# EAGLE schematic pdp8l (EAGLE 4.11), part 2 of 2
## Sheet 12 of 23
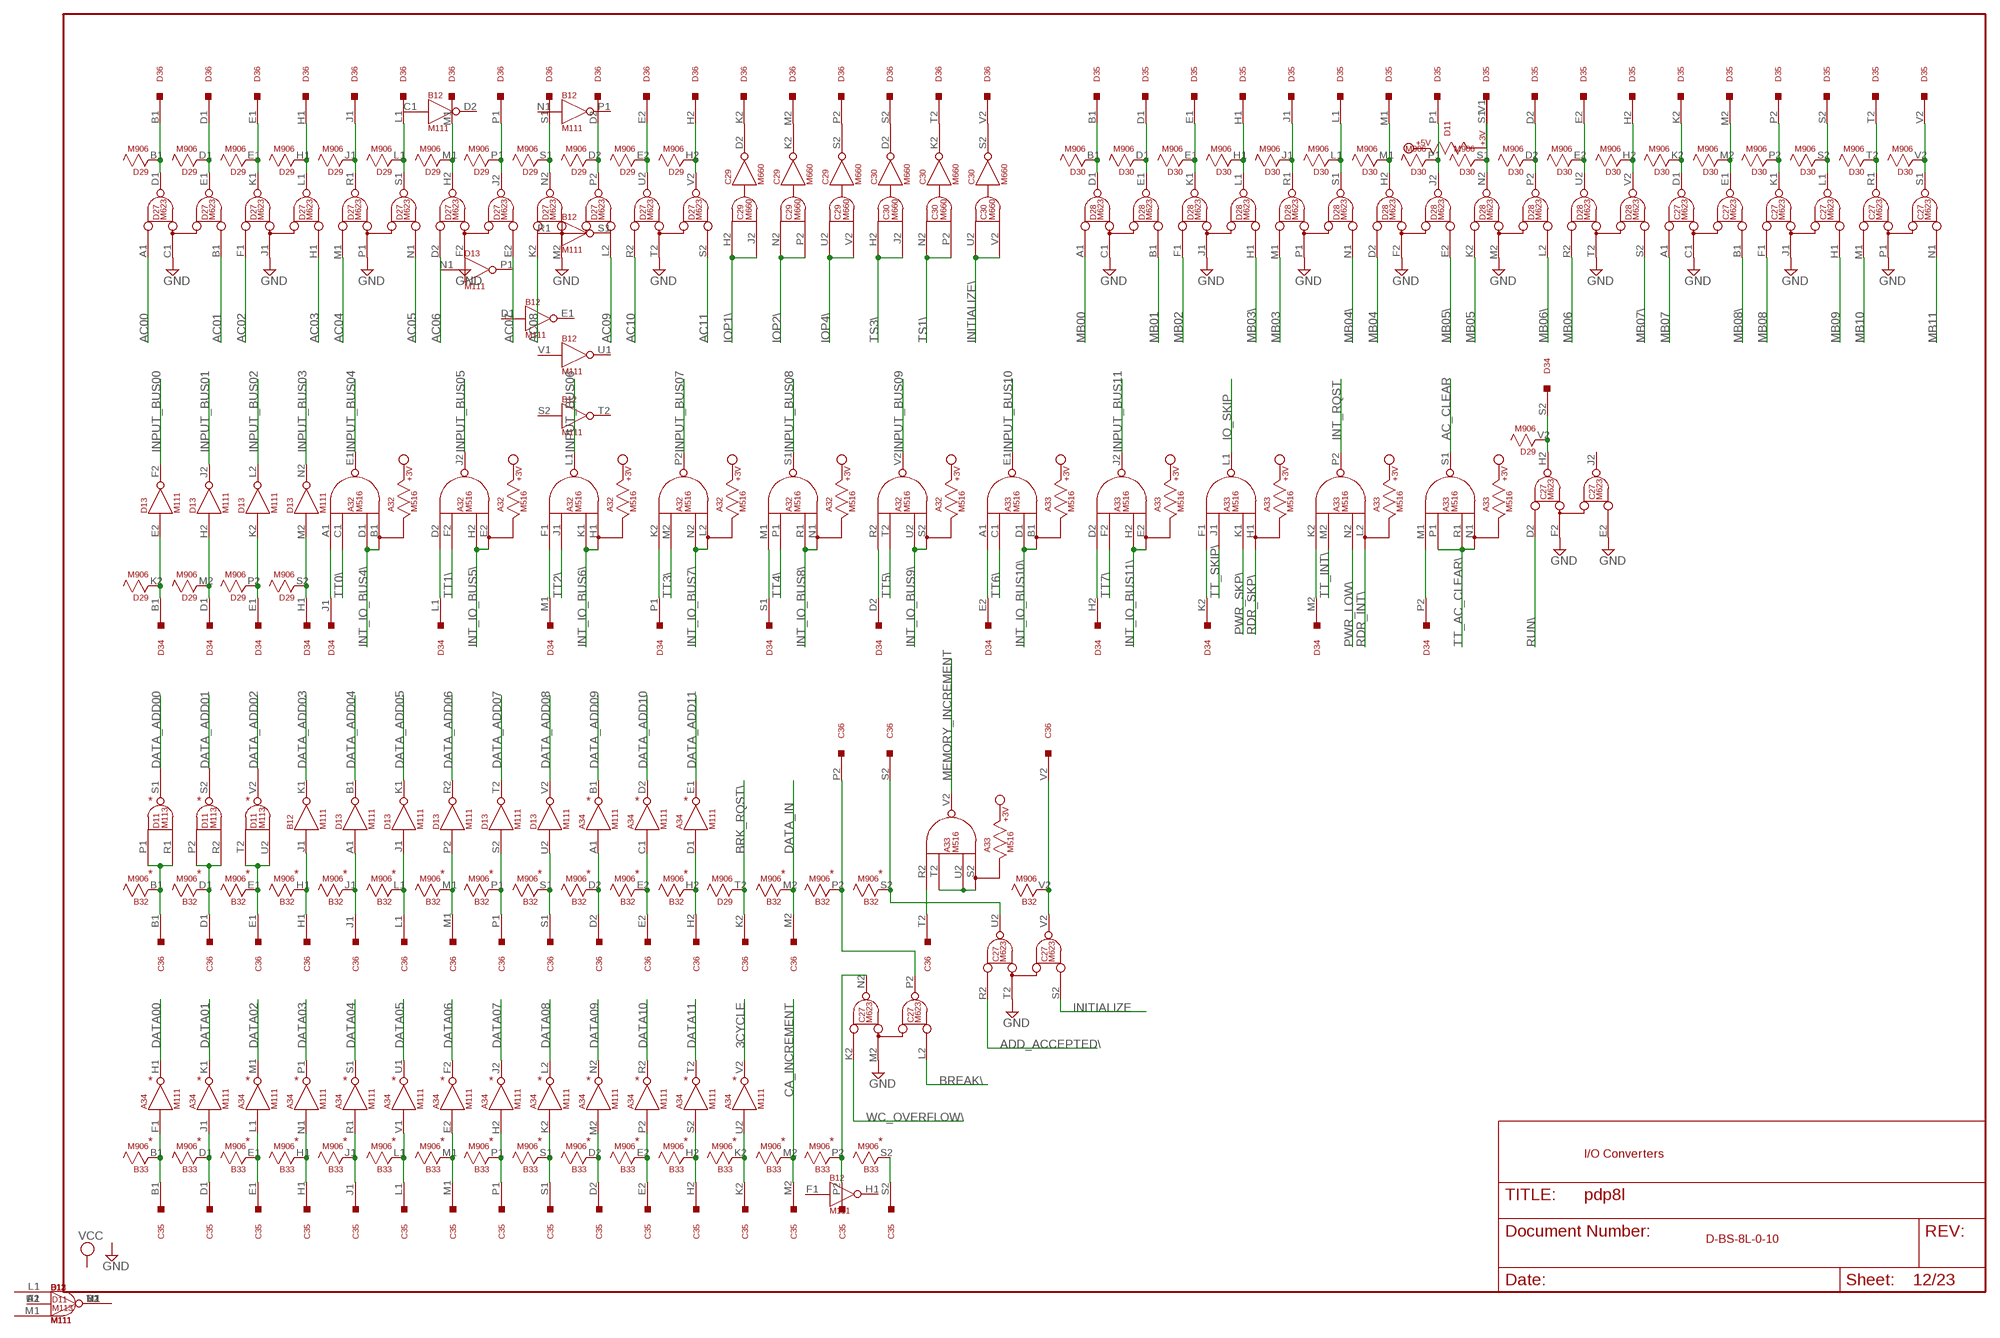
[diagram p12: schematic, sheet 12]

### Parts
A32  M516  [H807]
A33  M516  [H807]
A34  M111  [H807]
B32  M906  [H807]
B33  M906  [H807]
C27  M623  [H807]
C29  M660  [H807]
C30  M660  [H807]
C35  M903  [H807]
C36  M903  [H807]
D27  M623  [H807]
D28  M623  [H807]
D29  M906  [H807]
D30  M906  [H807]
D34  M903  [H807]
D35  M903  [H807]
D36  M903  [H807]

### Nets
3CYCLE: A34.V2(V2:OUT) ; also sheet 2
AC00: D27.A1(D1:A) ; also sheet 5,7
AC01: D27.B1(D1:B) ; also sheet 7
AC02: D27.F1(K1:A) ; also sheet 7
AC03: D27.H1(K1:B) ; also sheet 7
AC04: D27.M1(R1:A) ; also sheet 7,14,21
AC05: D27.N1(R1:B) ; also sheet 7,14,21
AC06: D27.D2(H2:A) ; also sheet 7,14,21
AC07: D27.E2(H2:B) ; also sheet 7,14,21
AC08: D27.K2(N2:A) ; also sheet 7,14,21
AC09: D27.L2(N2:B) ; also sheet 7,14,21
AC10: D27.R2(U2:A) ; also sheet 7,14,21
AC11: D27.S2(U2:B) ; also sheet 7,14,21
AC_CLEAR: A33.S1(S1:OUT) ; also sheet 3
ADD_ACCEPTED\: C27.R2(U2:A) ; also sheet 6
BREAK\: C27.L2(N2:B) ; also sheet 2
BRK_RQST\: C36.K2 D29.T2 ; also sheet 2
CA_INCREMENT: B33.M2 C35.M2 ; also sheet 4
DATA00: A34.H1(H1:OUT) ; also sheet 8
DATA01: A34.K1(K1:OUT) ; also sheet 8
DATA02: A34.M1(M1:OUT) ; also sheet 8
DATA03: A34.P1(P1:OUT) ; also sheet 9
DATA04: A34.S1(S1:OUT) ; also sheet 9
DATA05: A34.U1(U1:OUT) ; also sheet 9
DATA06: A34.F2(F2:OUT) ; also sheet 10
DATA07: A34.J2(J2:OUT) ; also sheet 10
DATA08: A34.L2(L2:OUT) ; also sheet 10
DATA09: A34.N2(N2:OUT) ; also sheet 11
DATA10: A34.R2(R2:OUT) ; also sheet 11
DATA11: A34.T2(T2:OUT) ; also sheet 11
DATA_ADD00: D11.S1(S1:OUT) ; also sheet 8
DATA_ADD01: D11.S2(S2:OUT) ; also sheet 8
DATA_ADD02: D11.V2(V2:OUT) ; also sheet 8
DATA_ADD03: B12.K1(K1:OUT) ; also sheet 9
DATA_ADD04: D13.B1(B1:OUT) ; also sheet 9
DATA_ADD05: D13.K1(K1:OUT) ; also sheet 9
DATA_ADD06: D13.R2(R2:OUT) ; also sheet 10
DATA_ADD07: D13.T2(T2:OUT) ; also sheet 10
DATA_ADD08: D13.V2(V2:OUT) ; also sheet 10
DATA_ADD09: A34.B1(B1:OUT) ; also sheet 11
DATA_ADD10: A34.D2(D2:OUT) ; also sheet 11
DATA_ADD11: A34.E1(E1:OUT) ; also sheet 11
DATA_IN: B32.M2 C36.M2 ; also sheet 3
GND [Supply]: C27.C1(D1:C) C27.E2(H2:B) C27.F2(H2:C) C27.J1(K1:C) C27.M2(N2:C) C27.P1(R1:C) C27.T2(U2:C) D27.C1(D1:C) D27.F2(H2:C) D27.J1(K1:C) D27.M2(N2:C) D27.P1(R1:C) D27.T2(U2:C) D28.C1(D1:C) D28.F2(H2:C) D28.J1(K1:C) D28.M2(N2:C) D28.P1(R1:C) D28.T2(U2:C) ; also sheet 1,3,8,9,10,11,13,14,15,16,19,20,21,23
INITIALIZE: C27.S2(U2:B) ; also sheet 1,13,14
INITIALIZE\: C30.U2(S:IN1) C30.V2(S:IN2) ; also sheet 1,21,22
INPUT_BUS00: D13.F2(F2:OUT) ; also sheet 8
INPUT_BUS01: D13.J2(J2:OUT) ; also sheet 8
INPUT_BUS02: D13.L2(L2:OUT) ; also sheet 8
INPUT_BUS03: D13.N2(N2:OUT) ; also sheet 9
INPUT_BUS04: A32.E1(E1:OUT) ; also sheet 9
INPUT_BUS05: A32.J2(J2:OUT) ; also sheet 9
INPUT_BUS06: A32.L1(L1:OUT) ; also sheet 10
INPUT_BUS07: A32.P2(P2:OUT) ; also sheet 10
INPUT_BUS08: A32.S1(S1:OUT) ; also sheet 10
INPUT_BUS09: A32.V2(V2:OUT) ; also sheet 11
INPUT_BUS10: A33.E1(E1:OUT) ; also sheet 11
INPUT_BUS11: A33.J2(J2:OUT) ; also sheet 11
INT_IO_BUS4\: A32.B1(E1:IN2) A32.D1(E1:IN4) ; also sheet 22
INT_IO_BUS5\: A32.E2(J2:IN2) A32.H2(J2:IN4) ; also sheet 22
INT_IO_BUS6\: A32.H1(L1:IN2) A32.K1(L1:IN4) ; also sheet 22
INT_IO_BUS7\: A32.L2(P2:IN2) A32.N2(P2:IN4) ; also sheet 22
INT_IO_BUS8\: A32.N1(S1:IN2) A32.R1(S1:IN4) ; also sheet 22
INT_IO_BUS9\: A32.S2(V2:IN2) A32.U2(V2:IN4) ; also sheet 22
INT_IO_BUS10\: A33.B1(E1:IN2) A33.D1(E1:IN4) ; also sheet 22
INT_IO_BUS11\: A33.E2(J2:IN2) A33.H2(J2:IN4) ; also sheet 22
INT_RQST: A33.P2(P2:OUT) ; also sheet 6
IO_SKIP: A33.L1(L1:OUT) ; also sheet 5
IOP1\: C29.H2(D:IN1) C29.J2(D:IN2) ; also sheet 1,3
IOP2\: C29.N2(K:IN1) C29.P2(K:IN2) ; also sheet 1,3
IOP4\: C29.U2(S:IN1) C29.V2(S:IN2) ; also sheet 1,3
MB00: D28.A1(D1:A) ; also sheet 7,23
MB01: D28.B1(D1:B) ; also sheet 7,23
MB02: D28.F1(K1:A) ; also sheet 7,23
MB03: D28.M1(R1:A) ; also sheet 2,7,23
MB03\: D28.H1(K1:B) ; also sheet 2,3,6,7,13,14,16,20,21,22,23
MB04: D28.D2(H2:A) ; also sheet 3,7,23
MB04\: D28.N1(R1:B) ; also sheet 3,6,7,13,14,20,21,22,23
MB05: D28.K2(N2:A) ; also sheet 3,5,7,20,23
MB05\: D28.E2(H2:B) ; also sheet 3,6,7,13,14,21,22,23
MB06: D28.R2(U2:A) ; also sheet 3,5,7,14,23
MB06\: D28.L2(N2:B) ; also sheet 3,6,7,13,20,21,22,23
MB07: C27.A1(D1:A) ; also sheet 3,5,7,13,21,23
MB07\: D28.S2(U2:B) ; also sheet 3,6,7,14,20,22,23
MB08: C27.F1(K1:A) ; also sheet 4,5,7,13,22,23
MB08\: C27.B1(D1:B) ; also sheet 4,5,6,7,14,16,20,21,23
MB09: C27.H1(K1:B) ; also sheet 1,3,4,7,23
MB10: C27.M1(R1:A) ; also sheet 1,4,7,23
MB11: C27.N1(R1:B) ; also sheet 1,4,7,23
MEMORY_INCREMENT: A33.V2(V2:OUT) ; also sheet 4,6
N$113: C30.S2(S:OUT) D36.V2
N$114: C30.K2(K:OUT) D36.T2
N$115: C30.D2(D:OUT) D36.S2
N$117: C29.S2(S:OUT) D36.P2
N$118: C29.K2(K:OUT) D36.M2
N$119: C29.D2(D:OUT) D36.K2
N$120: D27.D1(D1:D) D29.B1 D36.B1
N$121: D27.E1(D1:E) D29.D1 D36.D1
N$122: D27.K1(K1:D) D29.E1 D36.E1
N$124: D27.L1(K1:E) D29.H1 D36.H1
N$125: D27.R1(R1:D) D29.J1 D36.J1
N$126: D27.S1(R1:E) D29.L1 D36.L1
N$127: D27.H2(H2:D) D29.M1 D36.M1
N$128: D27.J2(H2:E) D29.P1 D36.P1
N$129: D27.N2(N2:D) D29.S1 D36.S1
N$130: D27.P2(N2:E) D29.D2 D36.D2
N$131: D27.U2(U2:D) D29.E2 D36.E2
N$132: D27.V2(U2:E) D29.H2 D36.H2
N$133: D28.D1(D1:D) D30.B1 D35.B1
N$134: D28.E1(D1:E) D30.D1 D35.D1
N$135: D28.K1(K1:D) D30.E1 D35.E1
N$136: D28.L1(K1:E) D30.H1 D35.H1
N$137: D28.R1(R1:D) D30.J1 D35.J1
N$138: D28.S1(R1:E) D30.L1 D35.L1
N$139: D28.H2(H2:D) D30.M1 D35.M1
N$140: D28.J2(H2:E) D30.P1 D35.P1
N$141: D28.N2(N2:D) D30.S1 D35.S1
N$142: D28.P2(N2:E) D30.D2 D35.D2
N$143: D28.U2(U2:D) D30.E2 D35.E2
N$144: D28.V2(U2:E) D30.H2 D35.H2
N$145: C27.D1(D1:D) D30.K2 D35.K2
N$146: C27.E1(D1:E) D30.M2 D35.M2
N$147: C27.K1(K1:D) D30.P2 D35.P2
N$148: C27.L1(K1:E) D30.S2 D35.S2
N$149: C27.R1(R1:D) D30.T2 D35.T2
N$150: C27.S1(R1:E) D30.V2 D35.V2
N$151: D13.E2(F2:IN) D29.K2 D34.B1
N$152: D13.H2(J2:IN) D29.M2 D34.D1
N$153: D13.K2(L2:IN) D29.P2 D34.E1
N$154: D13.M2(N2:IN) D29.S2 D34.H1
N$155: A32.A1(E1:IN) D34.J1
N$156: A32.D2(J2:IN) D34.L1
N$157: B32.B1 C36.B1 D11.P1(S1:IN1) D11.R1(S1:IN2)
N$158: B32.D1 C36.D1 D11.P2(S2:IN1) D11.R2(S2:IN2)
N$159: A32.F1(L1:IN) D34.M1
N$160: B32.E1 C36.E1 D11.T2(V2:IN1) D11.U2(V2:IN2)
N$161: A33.R2(V2:IN) C36.T2
N$162: A32.K2(P2:IN) D34.P1
N$163: A33.S2(V2:IN2) A33.T2(V2:IN3) A33.U2(V2:IN4)
N$164: B32.J1 C36.J1 D13.A1(B1:IN)
N$165: A32.M1(S1:IN) D34.S1
N$166: C27.H2(H2:D) D29.V2 D34.S2
N$167: B12.J1(K1:IN) B32.H1 C36.H1
N$168: B32.L1 C36.L1 D13.J1(K1:IN)
N$169: B32.M1 C36.M1 D13.P2(R2:IN)
N$170: A32.R2(V2:IN) D34.D2
N$171: B32.P1 C36.P1 D13.S2(T2:IN)
N$172: A33.A1(E1:IN) D34.E2
N$173: B32.S1 C36.S1 D13.U2(V2:IN)
N$174: A34.A1(B1:IN) B32.D2 C36.D2
N$175: A33.D2(J2:IN) D34.H2
N$176: A34.C1(D2:IN) B32.E2 C36.E2
N$177: A34.D1(E1:IN) B32.H2 C36.H2
N$178: B32.P2 C27.P2(N2:E) C36.P2
N$179: B32.S2 C27.U2(U2:D) C36.S2
N$180: A33.F1(L1:IN) D34.K2
N$181: B32.V2 C27.V2(U2:E) C36.V2
N$182: A34.F1(H1:IN) B33.B1 C35.B1
N$183: A34.J1(K1:IN) B33.D1 C35.D1
N$184: A33.M1(S1:IN) D34.P2
N$185: A34.L1(M1:IN) B33.E1 C35.E1
N$186: A33.K2(P2:IN) D34.M2
N$187: A34.N1(P1:IN) B33.H1 C35.H1
N$188: A34.R1(S1:IN) B33.J1 C35.J1
N$189: A34.V1(U1:IN) B33.L1 C35.L1
N$190: A34.E2(F2:IN) B33.M1 C35.M1
N$191: A34.H2(J2:IN) B33.P1 C35.P1
N$192: A34.K2(L2:IN) B33.S1 C35.S1
N$193: A34.M2(N2:IN) B33.D2 C35.D2
N$194: A34.P2(R2:IN) B33.E2 C35.E2
N$195: A34.S2(T2:IN) B33.H2 C35.H2
N$196: A34.U2(V2:IN) B33.K2 C35.K2
N$198: B33.P2 C27.N2(N2:D) C35.P2
N$199: B33.S2 C35.S2
PWR_LOW\: A33.N2(P2:IN4) ; also sheet 20
PWR_SKP\: A33.K1(L1:IN4) ; also sheet 20
RDR_INT\: A33.L2(P2:IN2) ; also sheet 21,22
RDR_SKP\: A33.H1(L1:IN2) ; also sheet 21,22
RUN\: C27.D2(H2:A) ; also sheet 1
TS1\: C30.N2(K:IN1) C30.P2(K:IN2) ; also sheet 1
TS3\: C30.H2(D:IN1) C30.J2(D:IN2) ; also sheet 1
TT0\: A32.C1(E1:IN3) ; also sheet 13
TT1\: A32.F2(J2:IN3) ; also sheet 13
TT2\: A32.J1(L1:IN3) ; also sheet 13
TT3\: A32.M2(P2:IN3) ; also sheet 13
TT4\: A32.P1(S1:IN3) ; also sheet 13
TT5\: A32.T2(V2:IN3) ; also sheet 13
TT6\: A33.C1(E1:IN3) ; also sheet 13
TT7\: A33.F2(J2:IN3) ; also sheet 13
TT_AC_CLEAR\: A33.N1(S1:IN2) A33.P1(S1:IN3) A33.R1(S1:IN4) ; also sheet 13
TT_INT\: A33.M2(P2:IN3) ; also sheet 14
TT_SKIP\: A33.J1(L1:IN3) ; also sheet 14
WC_OVERFLOW\: C27.K2(N2:A) ; also sheet 6
Unconnected: B32.K2 B32.T2 B33.T2 B33.V2 C27.J2(H2:E) C35.T2 C35.V2 D34.T2 D34.V2

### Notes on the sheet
- * | * | * | * | * | *
- * | * | * | * | * | * | * | * | * | * | * | * | * | * | *
- * | * | * | * | * | * | * | * | * | * | * | * | *
- * | * | * | * | * | * | * | * | * | * | * | * | * | * | * | *
- I/O Converters
- D-BS-8L-0-10

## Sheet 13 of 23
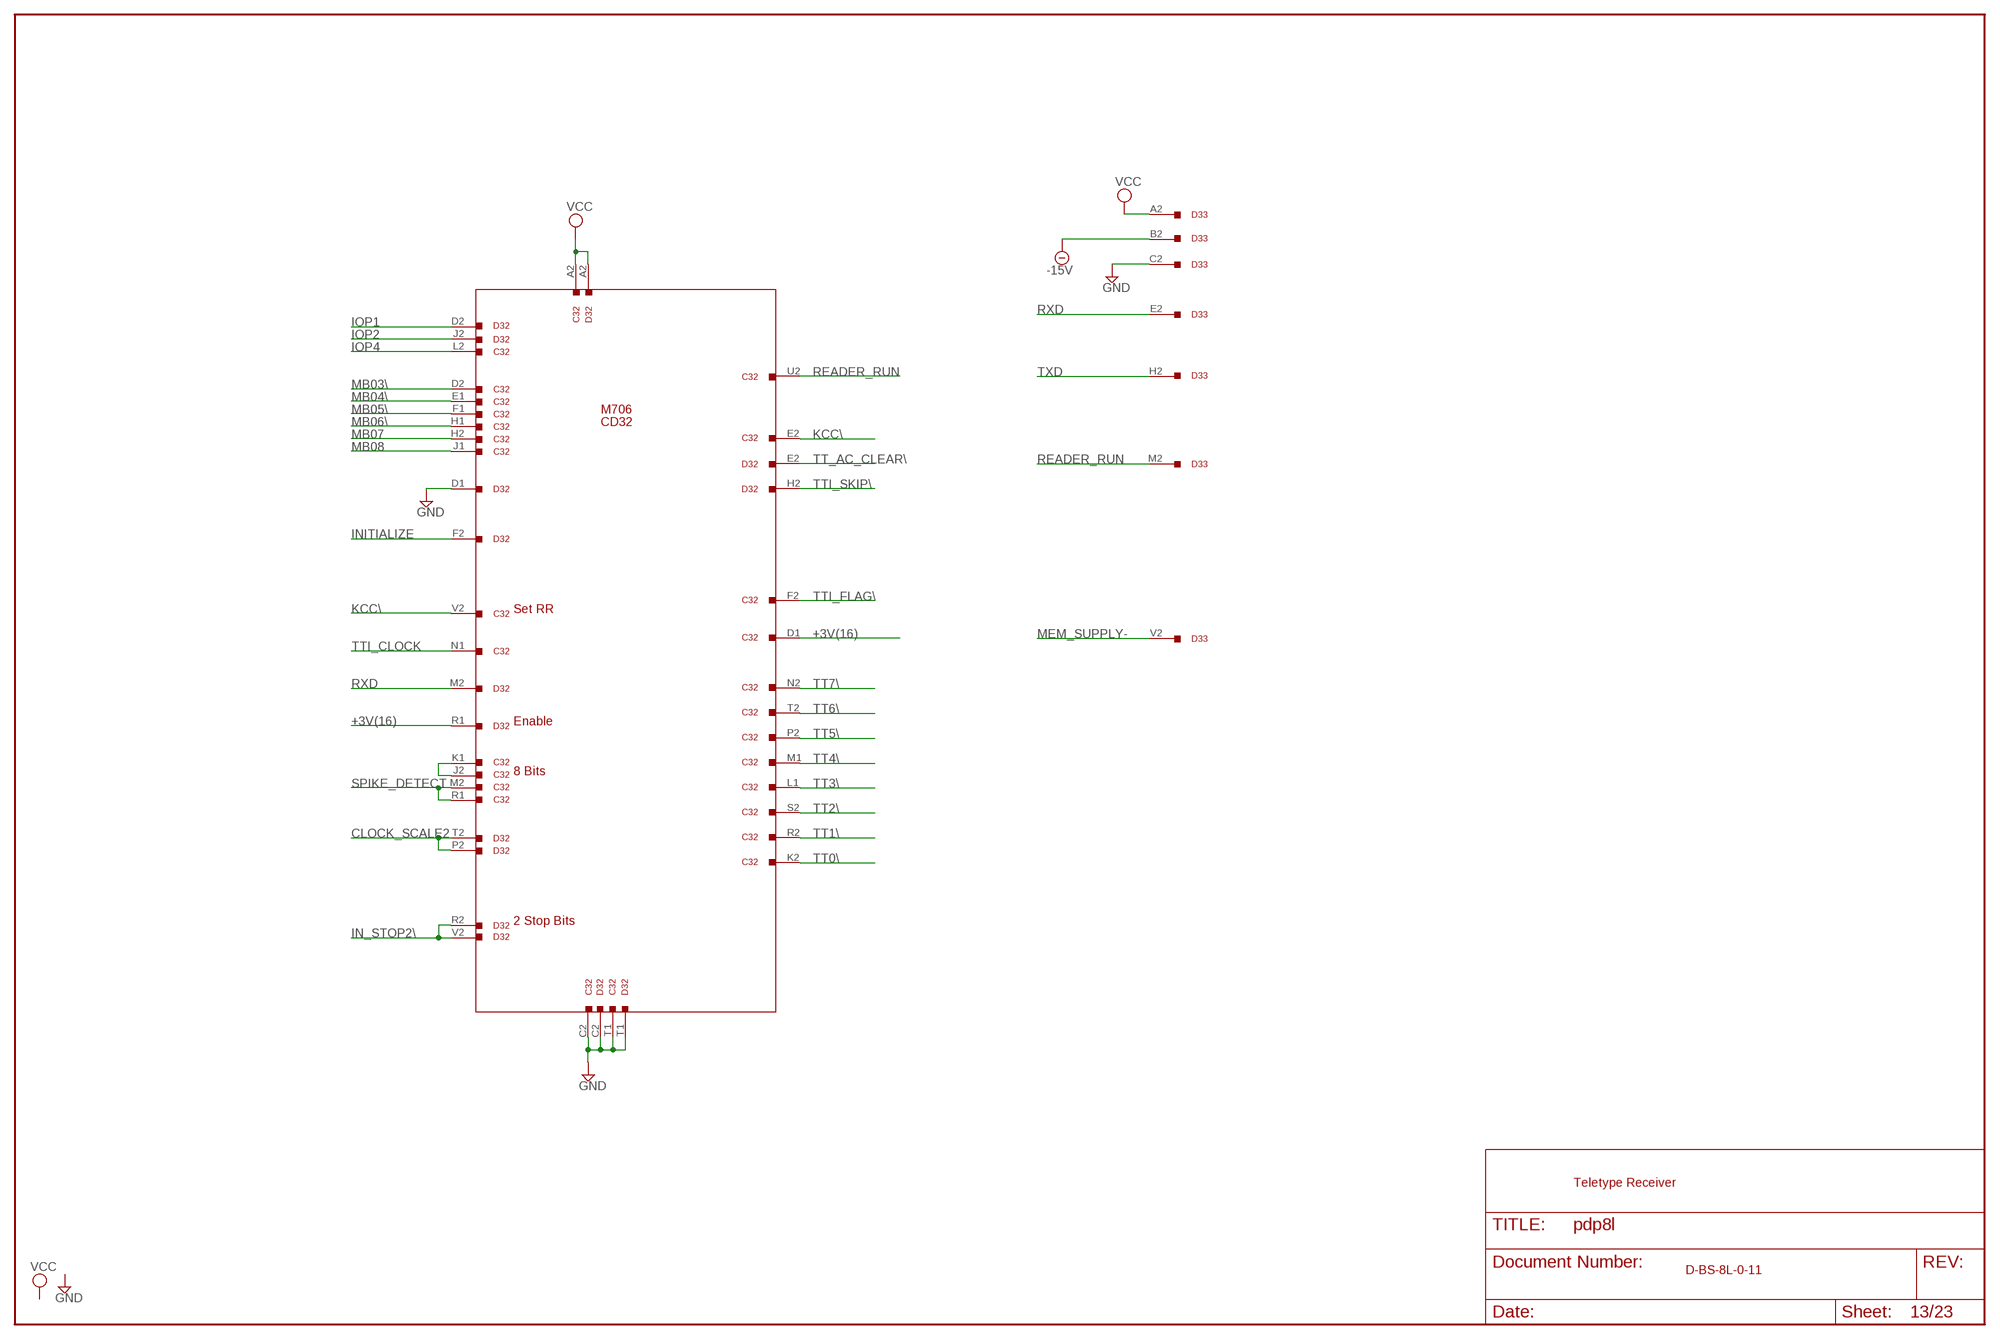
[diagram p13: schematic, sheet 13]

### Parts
C32  M916  [H807]
D32  M916  [H807]
D33  W076  W023  [H807]

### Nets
+3V(16): C32.D1 D32.R1
-15V [Supply]: D33.B2 ; also sheet 22
CLOCK_SCALE2: D32.P2 D32.T2
GND [Supply]: C32.C2 C32.T1 D32.C2 D32.D1 D32.T1 D33.C2 ; also sheet 1,3,8,9,10,11,12,14,15,16,19,20,21,23
IN_STOP2\: D32.R2 D32.V2
INITIALIZE: D32.F2 ; also sheet 1,12,14
IOP1: D32.D2 ; also sheet 1,14,21,22,23
IOP2: D32.J2 ; also sheet 1,14,20,21,22
IOP4: C32.L2 ; also sheet 1,14,21,22,23
KCC\: C32.E2 C32.V2
MB03\: C32.D2 ; also sheet 2,3,6,7,12,14,16,20,21,22,23
MB04\: C32.E1 ; also sheet 3,6,7,12,14,20,21,22,23
MB05\: C32.F1 ; also sheet 3,6,7,12,14,21,22,23
MB06\: C32.H1 ; also sheet 3,6,7,12,20,21,22,23
MB07: C32.H2 ; also sheet 3,5,7,12,21,23
MB08: C32.J1 ; also sheet 4,5,7,12,22,23
MEM_SUPPLY- [Supply]: D33.V2 ; also sheet 15,16
N$200: C32.J2 C32.K1
READER_RUN: C32.U2 D33.M2
RXD: D32.M2 D33.E2
SPIKE_DETECT: C32.M2 C32.R1
TT0\: C32.K2 ; also sheet 12
TT1\: C32.R2 ; also sheet 12
TT2\: C32.S2 ; also sheet 12
TT3\: C32.L1 ; also sheet 12
TT4\: C32.M1 ; also sheet 12
TT5\: C32.P2 ; also sheet 12
TT6\: C32.T2 ; also sheet 12
TT7\: C32.N2 ; also sheet 12
TT_AC_CLEAR\: D32.E2 ; also sheet 12
TTI_CLOCK: C32.N1 ; also sheet 14
TTI_FLAG\: C32.F2 ; also sheet 14
TTI_SKIP\: D32.H2 ; also sheet 14
TXD: D33.H2 ; also sheet 14
VCC [Supply]: C32.A2 D32.A2 D33.A2 ; also sheet 14,15,19,20
Unconnected: C32.A1 C32.B1 C32.B2 C32.C1 C32.P1 C32.S1 C32.U1 C32.V1 D32.A1 D32.B1 D32.B2 D32.C1 D32.E1 D32.F1 D32.H1 D32.J1 D32.K1 D32.K2 D32.L1 D32.L2 D32.M1 D32.N1 D32.N2 D32.P1 D32.S1 D32.S2 D32.U1 D32.U2 D32.V1 D33.D2 D33.F2 D33.J2 D33.K2 D33.L2 D33.N2 D33.P2 D33.R2 D33.S2 D33.T2 D33.U2

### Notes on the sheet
- M706
- CD32
- Set RR
- Enable
- 8 Bits
- 2 Stop Bits
- Teletype Receiver
- D-BS-8L-0-11

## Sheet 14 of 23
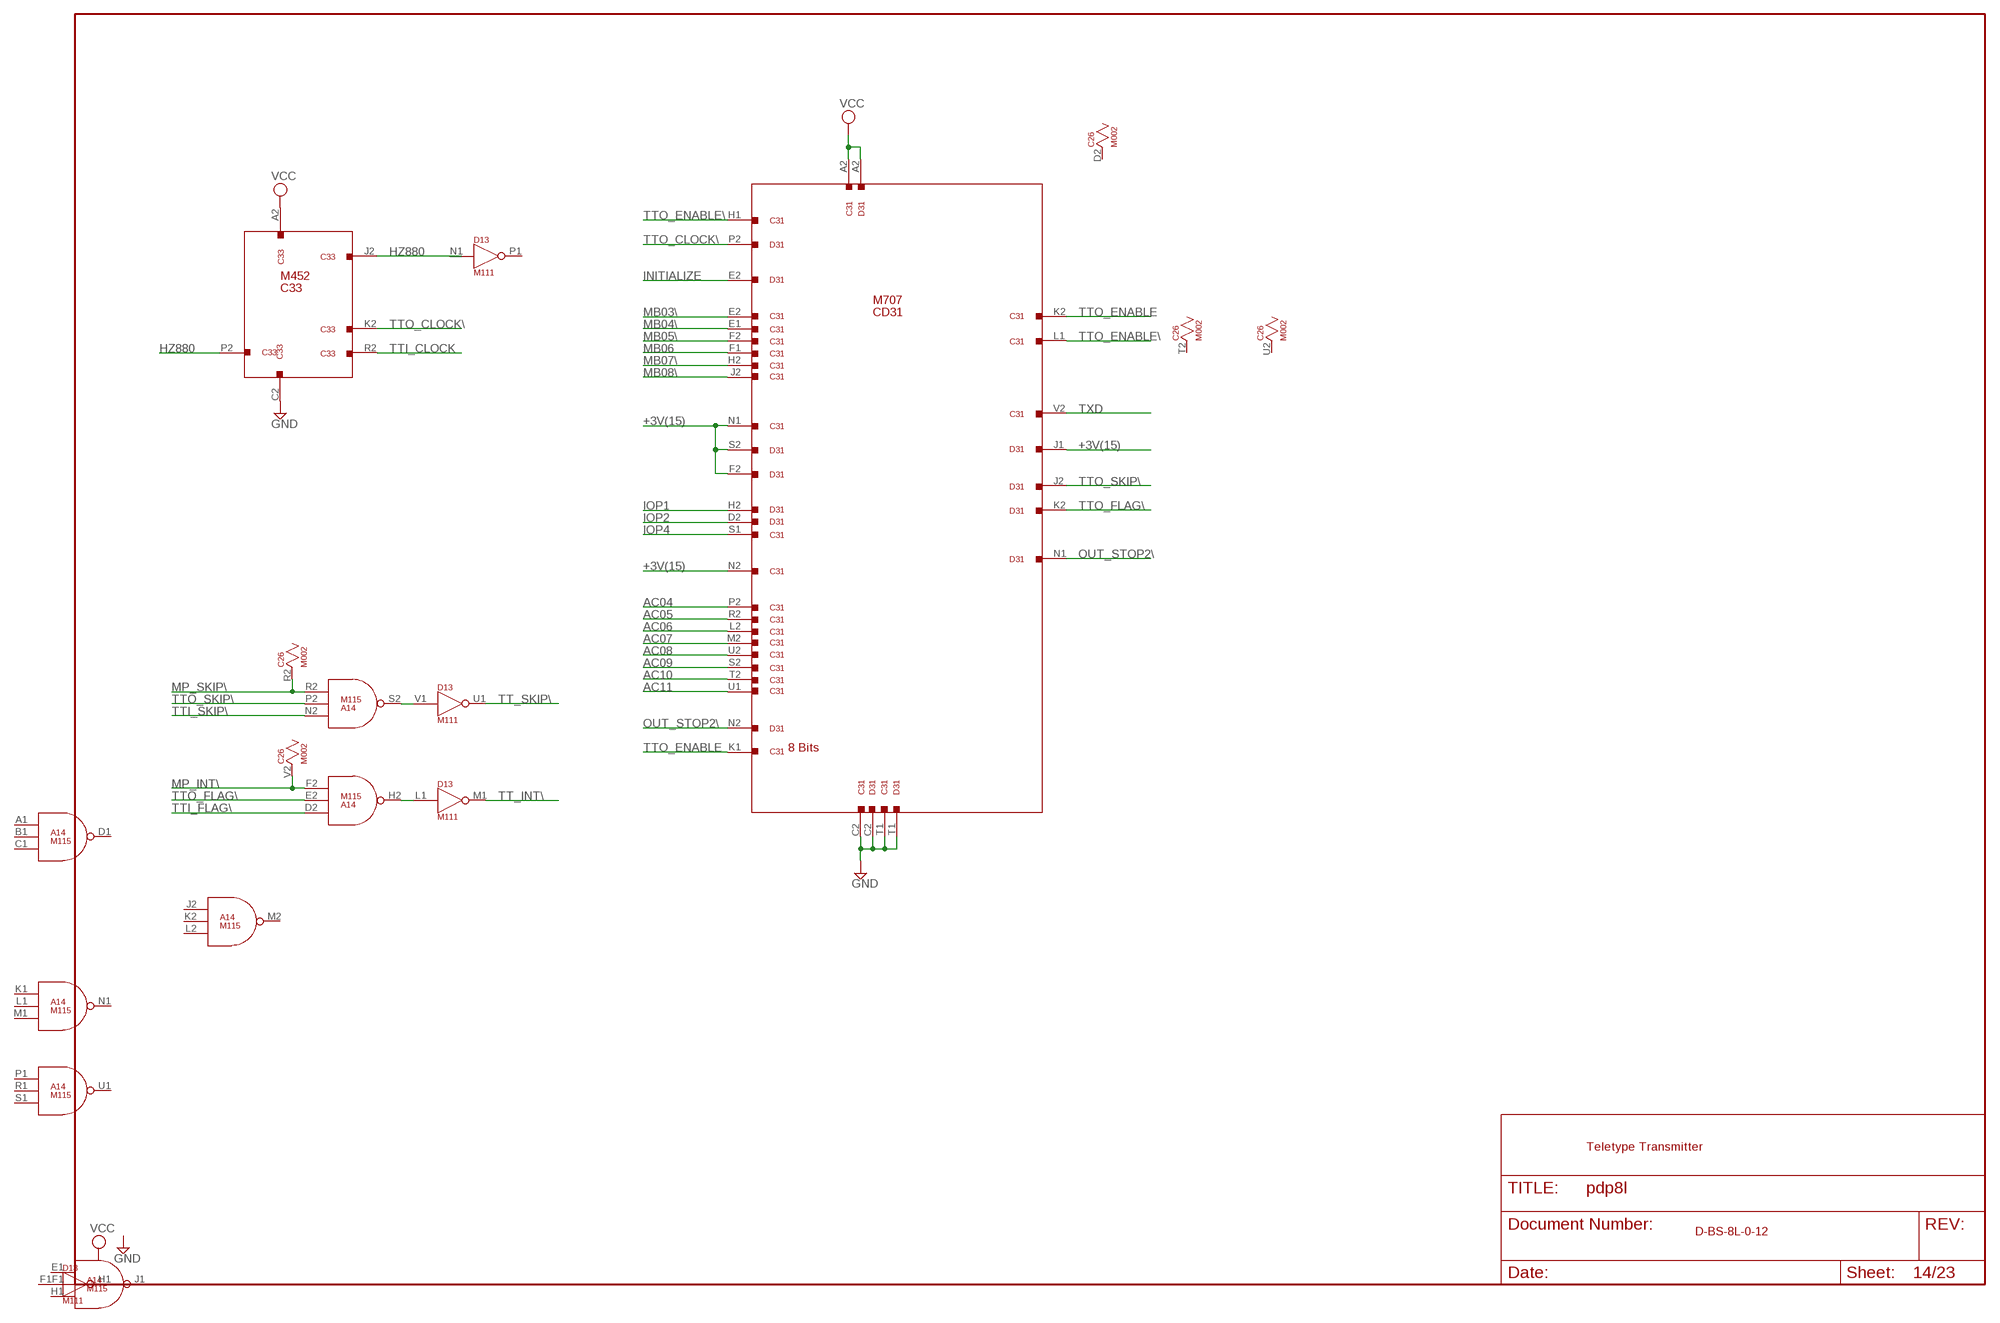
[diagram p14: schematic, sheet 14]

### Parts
C31  M916  [H807]
C33  W023  [H807]
D31  M916  [H807]

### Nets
+3V(15): C31.N1 C31.N2 D31.F2 D31.J1 D31.S2
AC04: C31.P2 ; also sheet 7,12,21
AC05: C31.R2 ; also sheet 7,12,21
AC06: C31.L2 ; also sheet 7,12,21
AC07: C31.M2 ; also sheet 7,12,21
AC08: C31.U2 ; also sheet 7,12,21
AC09: C31.S2 ; also sheet 7,12,21
AC10: C31.T2 ; also sheet 7,12,21
AC11: C31.U1 ; also sheet 7,12,21
GND [Supply]: C31.C2 C31.T1 C33.C2 D31.C2 D31.T1 ; also sheet 1,3,8,9,10,11,12,13,15,16,19,20,21,23
HZ880: C33.J2 C33.P2
INITIALIZE: D31.E2 ; also sheet 1,12,13
IOP1: D31.H2 ; also sheet 1,13,21,22,23
IOP2: D31.D2 ; also sheet 1,13,20,21,22
IOP4: C31.S1 ; also sheet 1,13,21,22,23
MB03\: C31.E2 ; also sheet 2,3,6,7,12,13,16,20,21,22,23
MB04\: C31.E1 ; also sheet 3,6,7,12,13,20,21,22,23
MB05\: C31.F2 ; also sheet 3,6,7,12,13,21,22,23
MB06: C31.F1 ; also sheet 3,5,7,12,23
MB07\: C31.H2 ; also sheet 3,6,7,12,20,22,23
MB08\: C31.J2 ; also sheet 4,5,6,7,12,16,20,21,23
MP_INT\: A14.F2(H2:IN3) C26.V2 ; also sheet 23
MP_SKIP\: A14.R2(S2:IN3) C26.R2 ; also sheet 23
N$108: A14.S2(S2:OUT) D13.V1(U1:IN)
N$197: A14.H2(H2:OUT) D13.L1(M1:IN)
OUT_STOP2\: D31.N1 D31.N2
TT_INT\: D13.M1(M1:OUT) ; also sheet 12
TT_SKIP\: D13.U1(U1:OUT) ; also sheet 12
TTI_CLOCK: C33.R2 ; also sheet 13
TTI_FLAG\: A14.D2(H2:IN1) ; also sheet 13
TTI_SKIP\: A14.N2(S2:IN1) ; also sheet 13
TTO_CLOCK\: C33.K2 D31.P2
TTO_ENABLE: C31.K1 C31.K2
TTO_ENABLE\: C31.H1 C31.L1
TTO_FLAG\: A14.E2(H2:IN2) D31.K2
TTO_SKIP\: A14.P2(S2:IN2) D31.J2
TXD: C31.V2 ; also sheet 13
VCC [Supply]: C31.A2 C33.A2 D31.A2 ; also sheet 13,15,19,20
Unconnected: C31.A1 C31.B1 C31.B2 C31.C1 C31.D1 C31.D2 C31.J1 C31.M1 C31.P1 C31.R1 C31.V1 C33.B2 C33.D2 C33.E2 C33.F2 C33.H2 C33.L2 C33.M2 C33.N2 C33.S2 C33.T2 C33.U2 C33.V2 D31.A1 D31.B1 D31.B2 D31.C1 D31.D1 D31.E1 D31.F1 D31.H1 D31.K1 D31.L1 D31.L2 D31.M1 D31.M2 D31.P1 D31.R1 D31.R2 D31.S1 D31.T2 D31.U1 D31.U2 D31.V1 D31.V2

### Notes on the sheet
- M452
- C33
- M707
- CD31
- 8 Bits
- Teletype Transmitter
- D-BS-8L-0-12

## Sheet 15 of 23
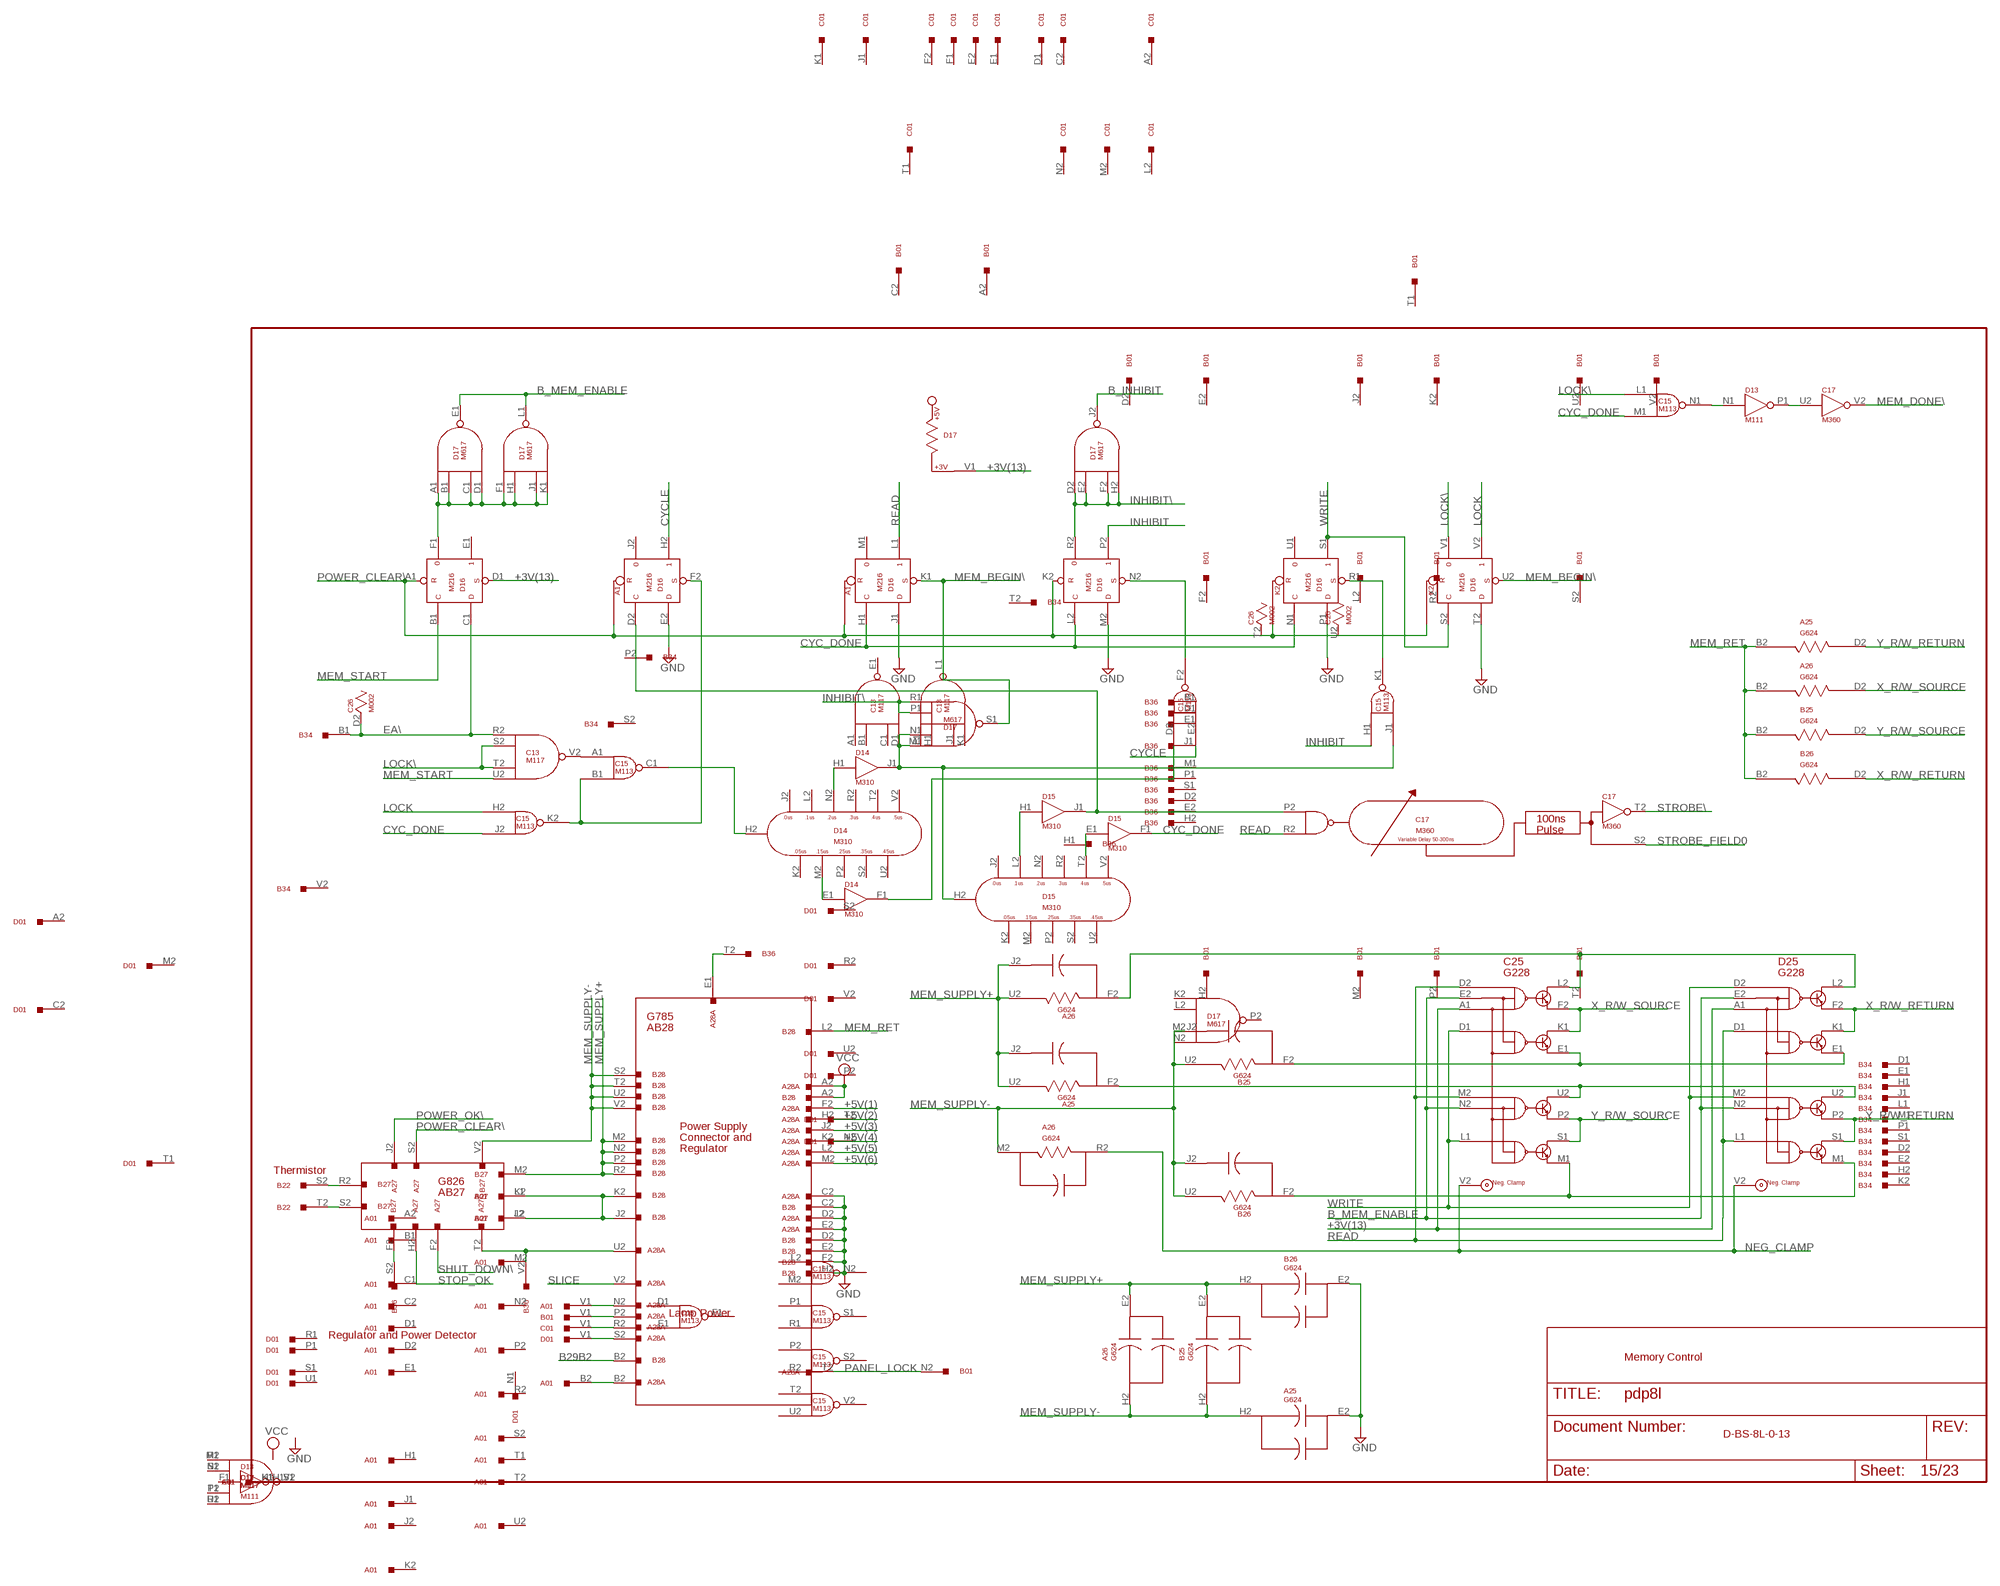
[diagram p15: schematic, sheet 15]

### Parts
A25  G624  [H807]
A26  G624  [H807]
A27  G826A  W023  [H807]
A28A  M916  [H807]
B22  W025B  W023  [H807]
B25  G624  [H807]
B26  G624  [H807]
B27  G826B  W023  [H807]
B28  G785B  W023  [H807]
C17  M360  [H807]
C25  G228  [H807]
D14  M310  [H807]
D15  M310  [H807]
D16  M216  M206X  [H807]
D17  M617  [H807]
D25  G228  [H807]

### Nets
+3V(13): C25.A1 D16.D1(E1:S) D17.V1 D25.A1 ; also sheet 5
+5V(1) [Supply]: A28A.F2
+5V(2) [Supply]: A28A.H2
+5V(3) [Supply]: A28A.J2
+5V(4) [Supply]: A28A.K2
+5V(5) [Supply]: A28A.L2
+5V(6) [Supply]: A28A.M2
A01B2 [Supply]: A01.B2 A28A.B2
A01V1 [Supply]: A01.V1 A28A.N2
B01V1 [Supply]: A28A.P2 B01.V1
B29B2 [Supply]: B28.B2 ; also sheet 22
B_INHIBIT: D17.J2(J2:OUT) ; also sheet 16
B_MEM_ENABLE: C25.E2 C25.N2 D17.E1(E1:OUT) D17.L1(L1:OUT) D25.E2 D25.N2 ; also sheet 16,17,18
C01V1 [Supply]: A28A.R2 C01.V1
CYC_DONE: C15.J2(K2:IN2) C15.M1(N1:IN2) D15.F1(F1:OUT) D16.H1(L1:C) D16.L2(P2:C) D16.N1(S1:C)
CYCLE: C15.E2(F2:IN2) D16.H2
D01V1 [Supply]: A28A.S2 D01.V1
EA\: B34.B1 C13.R2(V2:IN1) C26.D2 D16.C1(E1:D)
GND [Supply]: A25.E2 A28A.C2 A28A.D2 A28A.E2 B26.E2 B28.C2 B28.D2 B28.E2 B28.F2 B28.H2 D16.E2(H2:D) D16.J1(L1:D) D16.M2(P2:D) D16.P1(S1:D) D16.T2(V2:D) ; also sheet 1,3,8,9,10,11,12,13,14,16,19,20,21,23
INHIBIT: C15.H1(K1:IN1) D16.P2
INHIBIT\: D16.R2 D17.D2(J2:IN1) D17.E2(J2:IN2) D17.F2(J2:IN3) D17.H2(J2:IN4) D17.P1(S1:IN3) D17.R1(S1:IN4)
LOCK: C15.H2(K2:IN1) D16.V2
LOCK\: C13.S2(V2:IN2) C13.T2(V2:IN3) C15.L1(N1:IN1) D16.V1
MEM_BEGIN\: D16.K1(L1:S) D16.U2(V2:S) D17.S1(S1:OUT) ; also sheet 16
MEM_DONE\: C17.V2(V:OUT) ; also sheet 1,6
MEM_RET [Supply]: A25.B2 A26.B2 B25.B2 B26.B2 B28.L2
MEM_START: C13.U2(V2:IN4) D16.B1(E1:C) ; also sheet 1
MEM_SUPPLY+ [Supply]: A25.J2 A25.U2 A26.E2 A26.J2 A26.U2 B25.E2 B26.H2 B27.M2 B28.M2 B28.N2 B28.P2 B28.R2 ; also sheet 16
MEM_SUPPLY- [Supply]: A25.H2 A26.H2 A26.M2 B25.H2 B25.J2 B25.U2 B26.J2 B26.U2 B27.V2 B28.S2 B28.T2 B28.U2 B28.V2 ; also sheet 13,16
N$201: D16.F1 D17.A1(E1:IN1) D17.B1(E1:IN2) D17.C1(E1:IN3) D17.D1(E1:IN4) D17.F1(L1:IN1) D17.H1(L1:IN2) D17.J1(L1:IN3) D17.K1(L1:IN4)
N$203: C13.V2(V2:OUT) C15.A1(C1:IN1)
N$204: C15.B1(C1:IN2) C15.K2(K2:OUT) D16.F2(H2:S)
N$205: C15.C1(C1:OUT) D14.H2(H2:H2)
N$206: C17.P2(T:P) D15.J1(J1:OUT) D16.D2(H2:C)
N$207: C15.F2(F2:OUT) D16.N2(P2:S)
N$208: D14.H1(J1:IN) D14.N2(H2:N2)
N$209: D14.E1(F1:IN) D14.M2(H2:M2)
N$210: C15.J1(K1:IN2) D14.J1(J1:OUT) D15.H2(H2:H2) D17.M1(S1:IN1) D17.N1(S1:IN2)
N$211: D15.H1(J1:IN) D15.L2(H2:L2)
N$212: D15.E1(F1:IN) D15.T2(H2:T2)
N$213: C15.K1(K1:OUT) D16.R1(S1:S)
N$214: B22.T2 B27.S2
N$215: C15.D2(F2:IN1) D14.F1(F1:OUT)
N$216: B22.S2 B27.R2
N$217: B27.F2 B36.S2
N$218: A27.T2 A28A.U2 B36.V2
N$219: B27.J2 B27.K2 B28.J2 B28.K2
N$221: A26.F2 C25.L2 D25.L2
N$222: C17.U2(V:IN) D13.P1(P1:OUT)
N$223: C15.N1(N1:OUT) D13.N1(P1:IN)
N$224: B26.F2 C25.M1 D25.M1
N$225: B25.F2 C25.E1 D25.E1
N$226: A25.F2 C25.U2 D25.U2
N$414: A28A.E1 B36.T2
NEG_CLAMP: A26.R2 C25.V2 D25.V2 ; also sheet 17,18
PANEL_LOCK: A28A.T2 B01.N2
POWER_CLEAR\: A27.S2 D16.A1(E1:R) D16.K2(P2:R) ; also sheet 1
POWER_OK\: A27.J2 ; also sheet 1
READ: C17.R2(T:R) C25.D2 C25.M2 D16.L1 D25.D1 D25.L1
SHUT_DOWN\: A27.F2 ; also sheet 20
SLICE: A28A.V2 ; also sheet 16
STOP_OK: A27.H2 ; also sheet 1,20
STROBE\: C17.T2(T:T) ; also sheet 1,6
STROBE_FIELD0: C17.S2(T:S) ; also sheet 16
VCC [Supply]: A28A.A2 B28.A2 ; also sheet 13,14,19,20
WRITE: C25.D1 C25.L1 D16.S1 D16.S2(V2:C) D25.D2 D25.M2
X_R/W_RETURN: B26.D2 D25.F2 D25.K1 ; also sheet 17
X_R/W_SOURCE: A26.D2 C25.F2 C25.K1 ; also sheet 17
Y_R/W_RETURN: A25.D2 D25.P2 D25.S1 ; also sheet 18
Y_R/W_SOURCE: B25.D2 C25.P2 C25.S1 ; also sheet 18
Unconnected: A25.C2 A25.V2 A26.C2 A26.K2 A26.L2 A26.S2 A26.T2 A26.V2 A27.A2 A27.B2 A27.C2 A27.D2 A27.E2 A27.K2 A27.L2 A27.M2 A27.N2 A27.P2 A27.R2 A27.U2 A27.V2 A28A.A1 A28A.B1 A28A.C1 A28A.D1 A28A.F1 A28A.H1 A28A.J1 A28A.K1 A28A.L1 A28A.M1 A28A.N1 A28A.P1 A28A.R1 A28A.S1 A28A.T1 A28A.U1 A28A.V1 B22.A2 B22.B2 B22.U2 B22.V2 B25.C2 B25.V2 B26.C2 B26.V2 B27.A2 B27.B2 B27.C2 B27.D2 B27.E2 B27.H2 B27.L2 B27.N2 B27.P2 B27.T2 B27.U2 C25.F1(F1:H) C25.H1(F1:J) C25.H2(H2:H) C25.J1(F1:K) C25.J2(H2:J) C25.K2(H2:K) C25.N1(N1:H) C25.P1(N1:J) C25.R1(N1:K) C25.R2(R2:H) C25.S2(R2:J) C25.T2(R2:K) D14.J2(H2:J2) D14.K2(H2:K2) D14.L2(H2:L2) D14.P2(H2:P2) D14.R2(H2:R2) D14.S2(H2:S2) D14.T2(H2:T2) D14.U2(H2:U2) D14.V2(H2:V2) D15.J2(H2:J2) D15.K2(H2:K2) D15.M2(H2:M2) D15.N2(H2:N2) D15.P2(H2:P2) D15.R2(H2:R2) D15.S2(H2:S2) D15.U2(H2:U2) D15.V2(H2:V2) D16.E1 D16.J2 D16.M1 D16.U1 D17.U1 D25.F1(F1:H) D25.H1(F1:J) D25.H2(H2:H) D25.J1(F1:K) D25.J2(H2:J) D25.K2(H2:K) D25.N1(N1:H) D25.P1(N1:J) D25.R1(N1:K) D25.R2(R2:H) D25.S2(R2:J) D25.T2(R2:K)

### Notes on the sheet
- G785
- AB28
- Power Supply
- Connector and
- Regulator
- Thermistor
- G826
- AB27
- Lamp Power
- Regulator and Power Detector
- Memory Control
- D-BS-8L-0-13

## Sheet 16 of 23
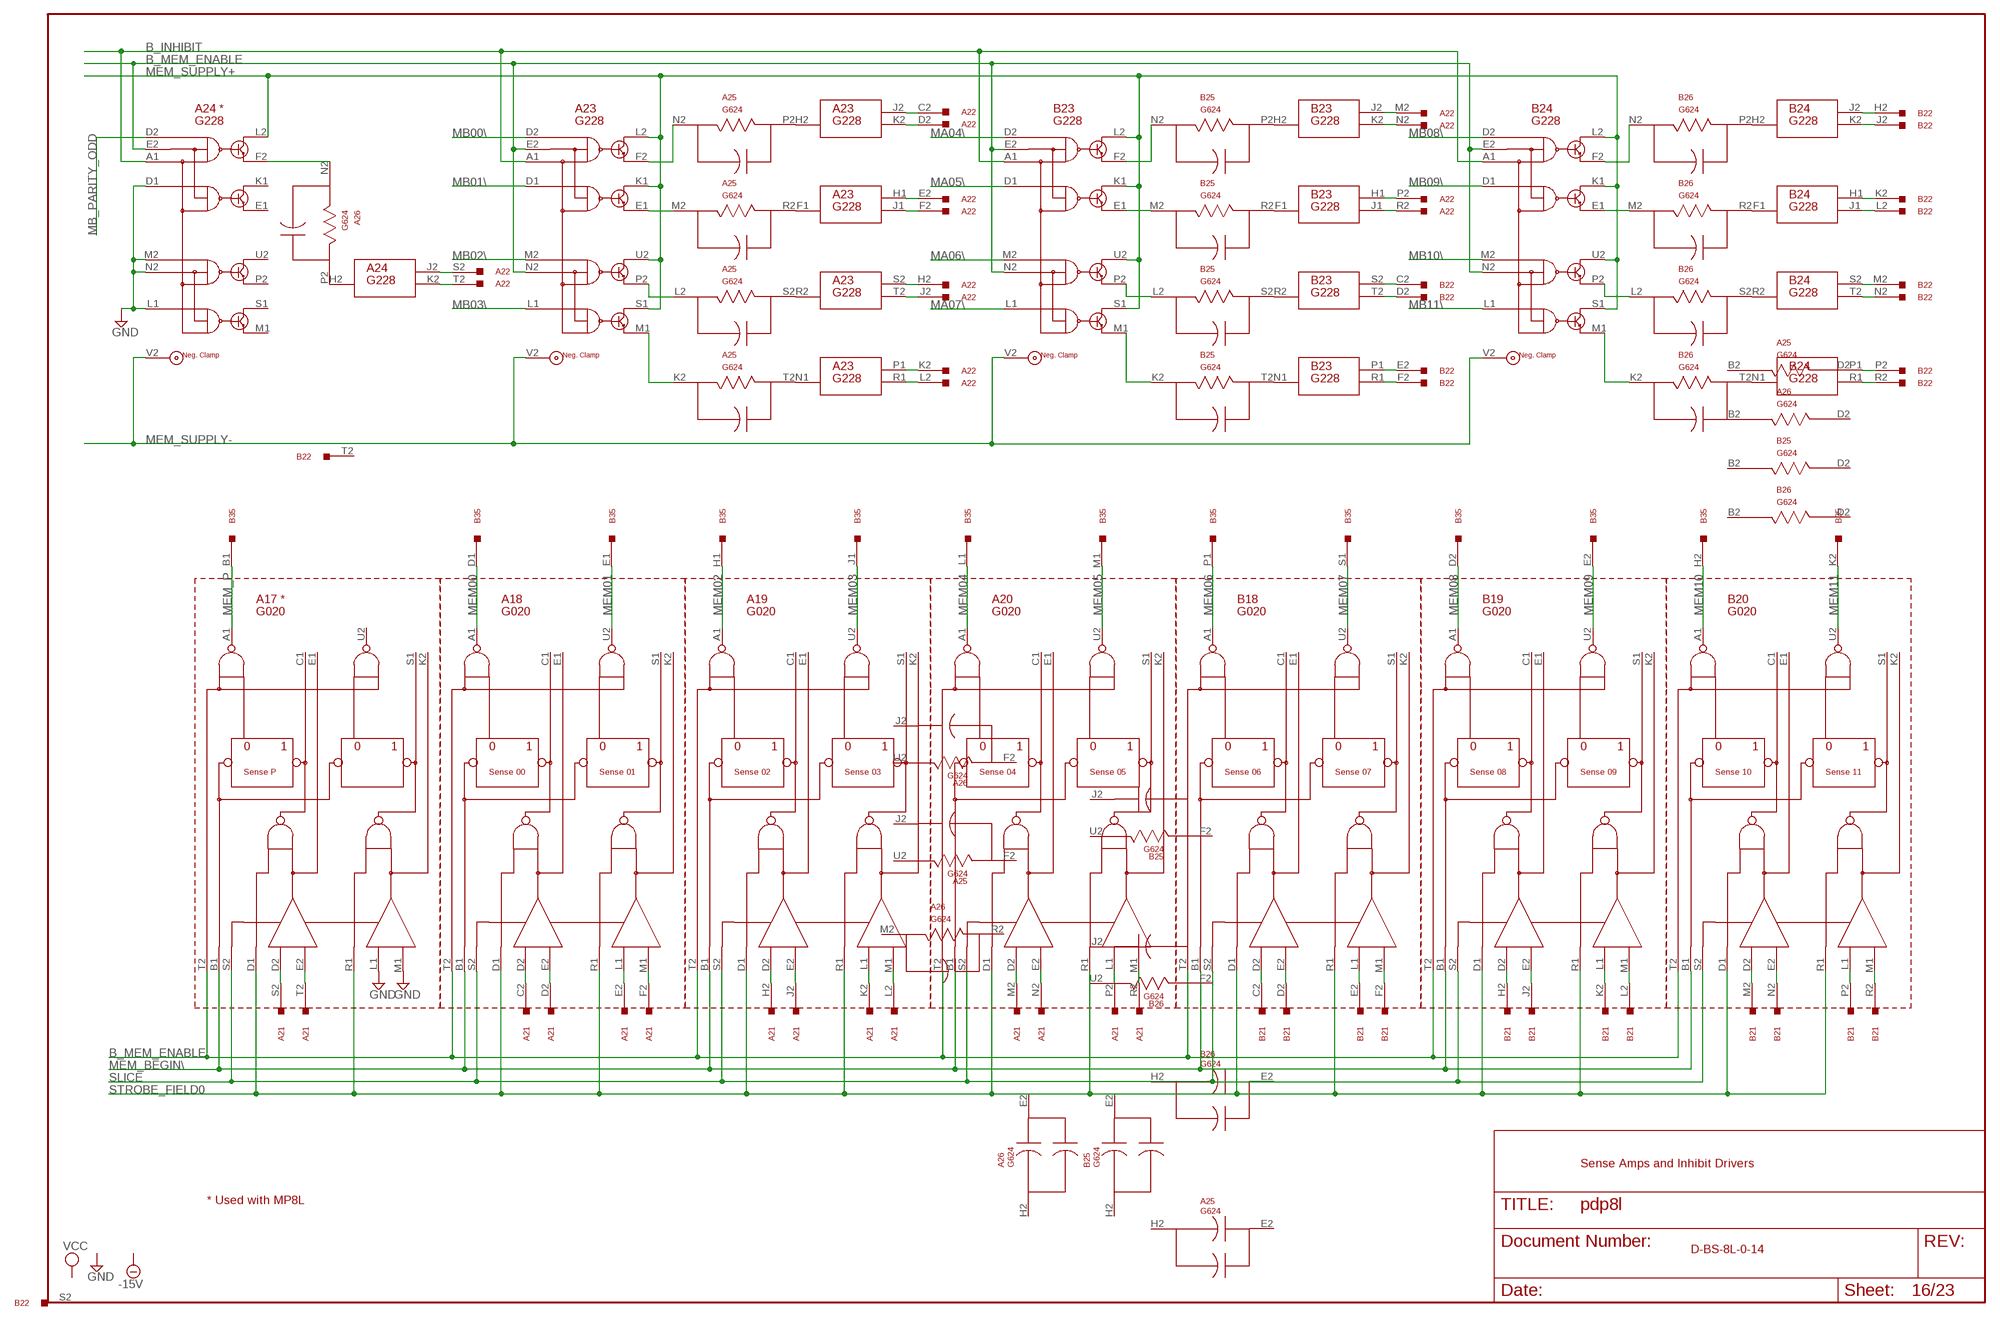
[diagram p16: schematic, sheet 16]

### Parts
A17  G020  [H807]
A18  G020  [H807]
A19  G020  [H807]
A20  G020  [H807]
A21  W025A  W023  [H807]
A22  W025A  W023  [H807]
A23  G228  [H807]
A24  G228  [H807]
B18  G020  [H807]
B19  G020  [H807]
B20  G020  [H807]
B21  W025B  W023  [H807]
B23  G228  [H807]
B24  G228  [H807]

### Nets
B_INHIBIT: A23.A1 A24.A1 B23.A1 B24.A1 ; also sheet 15
B_MEM_ENABLE: A17.T2 A18.T2 A19.T2 A20.T2 A23.E2 A23.N2 A24.E2 B18.T2 B19.T2 B20.T2 B23.E2 B23.N2 B24.E2 B24.N2 ; also sheet 15,17,18
GND [Supply]: A17.L1 A17.M1 A24.D1 A24.L1 A24.M2 A24.N2 ; also sheet 1,3,8,9,10,11,12,13,14,15,19,20,21,23
MA04\: B23.D2 ; also sheet 4,7,19
MA05\: B23.D1 ; also sheet 4,7,19
MA06\: B23.M2 ; also sheet 4,7,18,19
MA07\: B23.L1 ; also sheet 4,7,19
MB00\: A23.D2 ; also sheet 7,23
MB01\: A23.D1 ; also sheet 7,23
MB02\: A23.M2 ; also sheet 7,23
MB03\: A23.L1 ; also sheet 2,3,6,7,12,13,14,20,21,22,23
MB08\: B24.D2 ; also sheet 4,5,6,7,12,14,20,21,23
MB09\: B24.D1 ; also sheet 4,7,23
MB10\: B24.M2 ; also sheet 4,6,7,23
MB11\: B24.L1 ; also sheet 1,2,3,6,7,23
MB_PARITY_ODD: A24.D2 ; also sheet 23
MEM00: A18.A1 B35.D1 ; also sheet 2,8,23
MEM01: A18.U2 B35.E1 ; also sheet 2,8,23
MEM02: A19.A1 B35.H1 ; also sheet 2,8,23
MEM03: A19.U2 B35.J1 ; also sheet 9,23
MEM04: A20.A1 B35.L1 ; also sheet 9,23
MEM05: A20.U2 B35.M1 ; also sheet 9,23
MEM06: B18.A1 B35.P1 ; also sheet 10,23
MEM07: B18.U2 B35.S1 ; also sheet 10,23
MEM08: B19.A1 B35.D2 ; also sheet 10,23
MEM09: B19.U2 B35.E2 ; also sheet 11,23
MEM10: B20.A1 B35.H2 ; also sheet 11,23
MEM11: B20.U2 B35.K2 ; also sheet 11,23
MEM_BEGIN\: A17.B1 A18.B1 A19.B1 A20.B1 B18.B1 B19.B1 B20.B1 ; also sheet 15
MEM_P: A17.A1 B35.B1 ; also sheet 23
MEM_SUPPLY+ [Supply]: A23.K1 A23.L2 A23.S1 A23.U2 A24.L2 B23.K1 B23.L2 B23.S1 B23.U2 B24.K1 B24.L2 B24.S1 B24.U2 ; also sheet 15
MEM_SUPPLY- [Supply]: A23.V2 A24.V2 B23.V2 B24.V2 ; also sheet 13,15
N$227: A17.D2 A21.S2
N$228: A17.E2 A21.T2
N$229: A18.D2 A21.C2
N$230: A18.E2 A21.D2
N$231: A18.L1 A21.E2
N$232: A18.M1 A21.F2
N$233: A19.D2 A21.H2
N$234: A19.E2 A21.J2
N$235: A19.L1 A21.K2
N$236: A19.M1 A21.L2
N$237: A20.D2 A21.M2
N$238: A20.E2 A21.N2
N$239: A20.L1 A21.P2
N$240: A20.M1 A21.R2
N$241: B18.D2 B21.C2
N$242: B18.E2 B21.D2
N$243: B18.L1 B21.E2
N$244: B18.M1 B21.F2
N$245: B19.D2 B21.H2
N$246: B19.E2 B21.J2
N$247: B19.L1 B21.K2
N$248: B19.M1 B21.L2
N$249: B20.D2 B21.M2
N$250: B20.E2 B21.N2
N$251: B20.L1 B21.P2
N$252: B20.M1 B21.R2
N$253: A24.H2(H2:H) A26.P2
N$267: A22.T2 A24.K2(H2:K)
N$268: A22.S2 A24.J2(H2:J)
N$269: B23.M1 B25.K2
N$270: A23.F2 A25.N2
N$271: A24.F2 A26.N2
N$272: A23.E1 A25.M2
N$273: A23.P2 A25.L2
N$274: A23.M1 A25.K2
N$275: A23.H2(H2:H) A25.P2
N$276: A23.F1(F1:H) A25.R2
N$277: A23.N1(N1:H) A25.T2
N$278: A23.R2(R2:H) A25.S2
N$279: A22.D2 A23.K2(H2:K)
N$280: A22.C2 A23.J2(H2:J)
N$281: A22.E2 A23.H1(F1:J)
N$282: A22.F2 A23.J1(F1:K)
N$283: A22.H2 A23.S2(R2:J)
N$284: A22.J2 A23.T2(R2:K)
N$285: A22.L2 A23.R1(N1:K)
N$286: A22.K2 A23.P1(N1:J)
N$287: B23.P2 B25.L2
N$288: B23.E1 B25.M2
N$289: B23.F2 B25.N2
N$290: B23.H2(H2:H) B25.P2
N$291: B23.F1(F1:H) B25.R2
N$292: B23.R2(R2:H) B25.S2
N$293: B23.N1(N1:H) B25.T2
N$294: A22.M2 B23.J2(H2:J)
N$295: A22.N2 B23.K2(H2:K)
N$296: A22.R2 B23.J1(F1:K)
N$297: A22.P2 B23.H1(F1:J)
N$298: B22.C2 B23.S2(R2:J)
N$299: B22.D2 B23.T2(R2:K)
N$300: B22.E2 B23.P1(N1:J)
N$301: B22.F2 B23.R1(N1:K)
N$302: B24.M1 B26.K2
N$303: B24.P2 B26.L2
N$304: B24.E1 B26.M2
N$305: B24.F2 B26.N2
N$306: B24.H2(H2:H) B26.P2
N$307: B24.F1(F1:H) B26.R2
N$308: B24.R2(R2:H) B26.S2
N$309: B24.N1(N1:H) B26.T2
N$310: B22.L2 B24.J1(F1:K)
N$311: B22.K2 B24.H1(F1:J)
N$312: B22.J2 B24.K2(H2:K)
N$313: B22.H2 B24.J2(H2:J)
N$314: B22.M2 B24.S2(R2:J)
N$315: B22.N2 B24.T2(R2:K)
N$316: B22.P2 B24.P1(N1:J)
N$317: B22.R2 B24.R1(N1:K)
SLICE: A17.S2 A18.S2 A19.S2 A20.S2 B18.S2 B19.S2 B20.S2 ; also sheet 15
STROBE_FIELD0: A17.D1 A17.R1 A18.D1 A18.R1 A19.D1 A19.R1 A20.D1 A20.R1 B18.D1 B18.R1 B19.D1 B19.R1 B20.D1 B20.R1 ; also sheet 15
Unconnected: A17.C1 A17.E1 A17.K2 A17.S1 A17.U2 A18.C1 A18.E1 A18.K2 A18.S1 A19.C1 A19.E1 A19.K2 A19.S1 A20.C1 A20.E1 A20.K2 A20.S1 A21.A2 A21.B2 A21.U2 A21.V2 A22.A2 A22.B2 A22.U2 A22.V2 A24.E1 A24.F1(F1:H) A24.H1(F1:J) A24.J1(F1:K) A24.K1 A24.M1 A24.N1(N1:H) A24.P1(N1:J) A24.P2 A24.R1(N1:K) A24.R2(R2:H) A24.S1 A24.S2(R2:J) A24.T2(R2:K) A24.U2 B18.C1 B18.E1 B18.K2 B18.S1 B19.C1 B19.E1 B19.K2 B19.S1 B20.C1 B20.E1 B20.K2 B20.S1 B21.A2 B21.B2 B21.S2 B21.T2 B21.U2 B21.V2

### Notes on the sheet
- *
- *
- Sense P | Sense 00 | Sense 01 | Sense 02 | Sense 03 | Sense 04 | Sense 05 | Sense 06 | Sense 07 | Sense 08 | Sense 09 | Sense 10 | Sense 11
- Sense Amps and Inhibit Drivers
- * Used with MP8L
- D-BS-8L-0-14

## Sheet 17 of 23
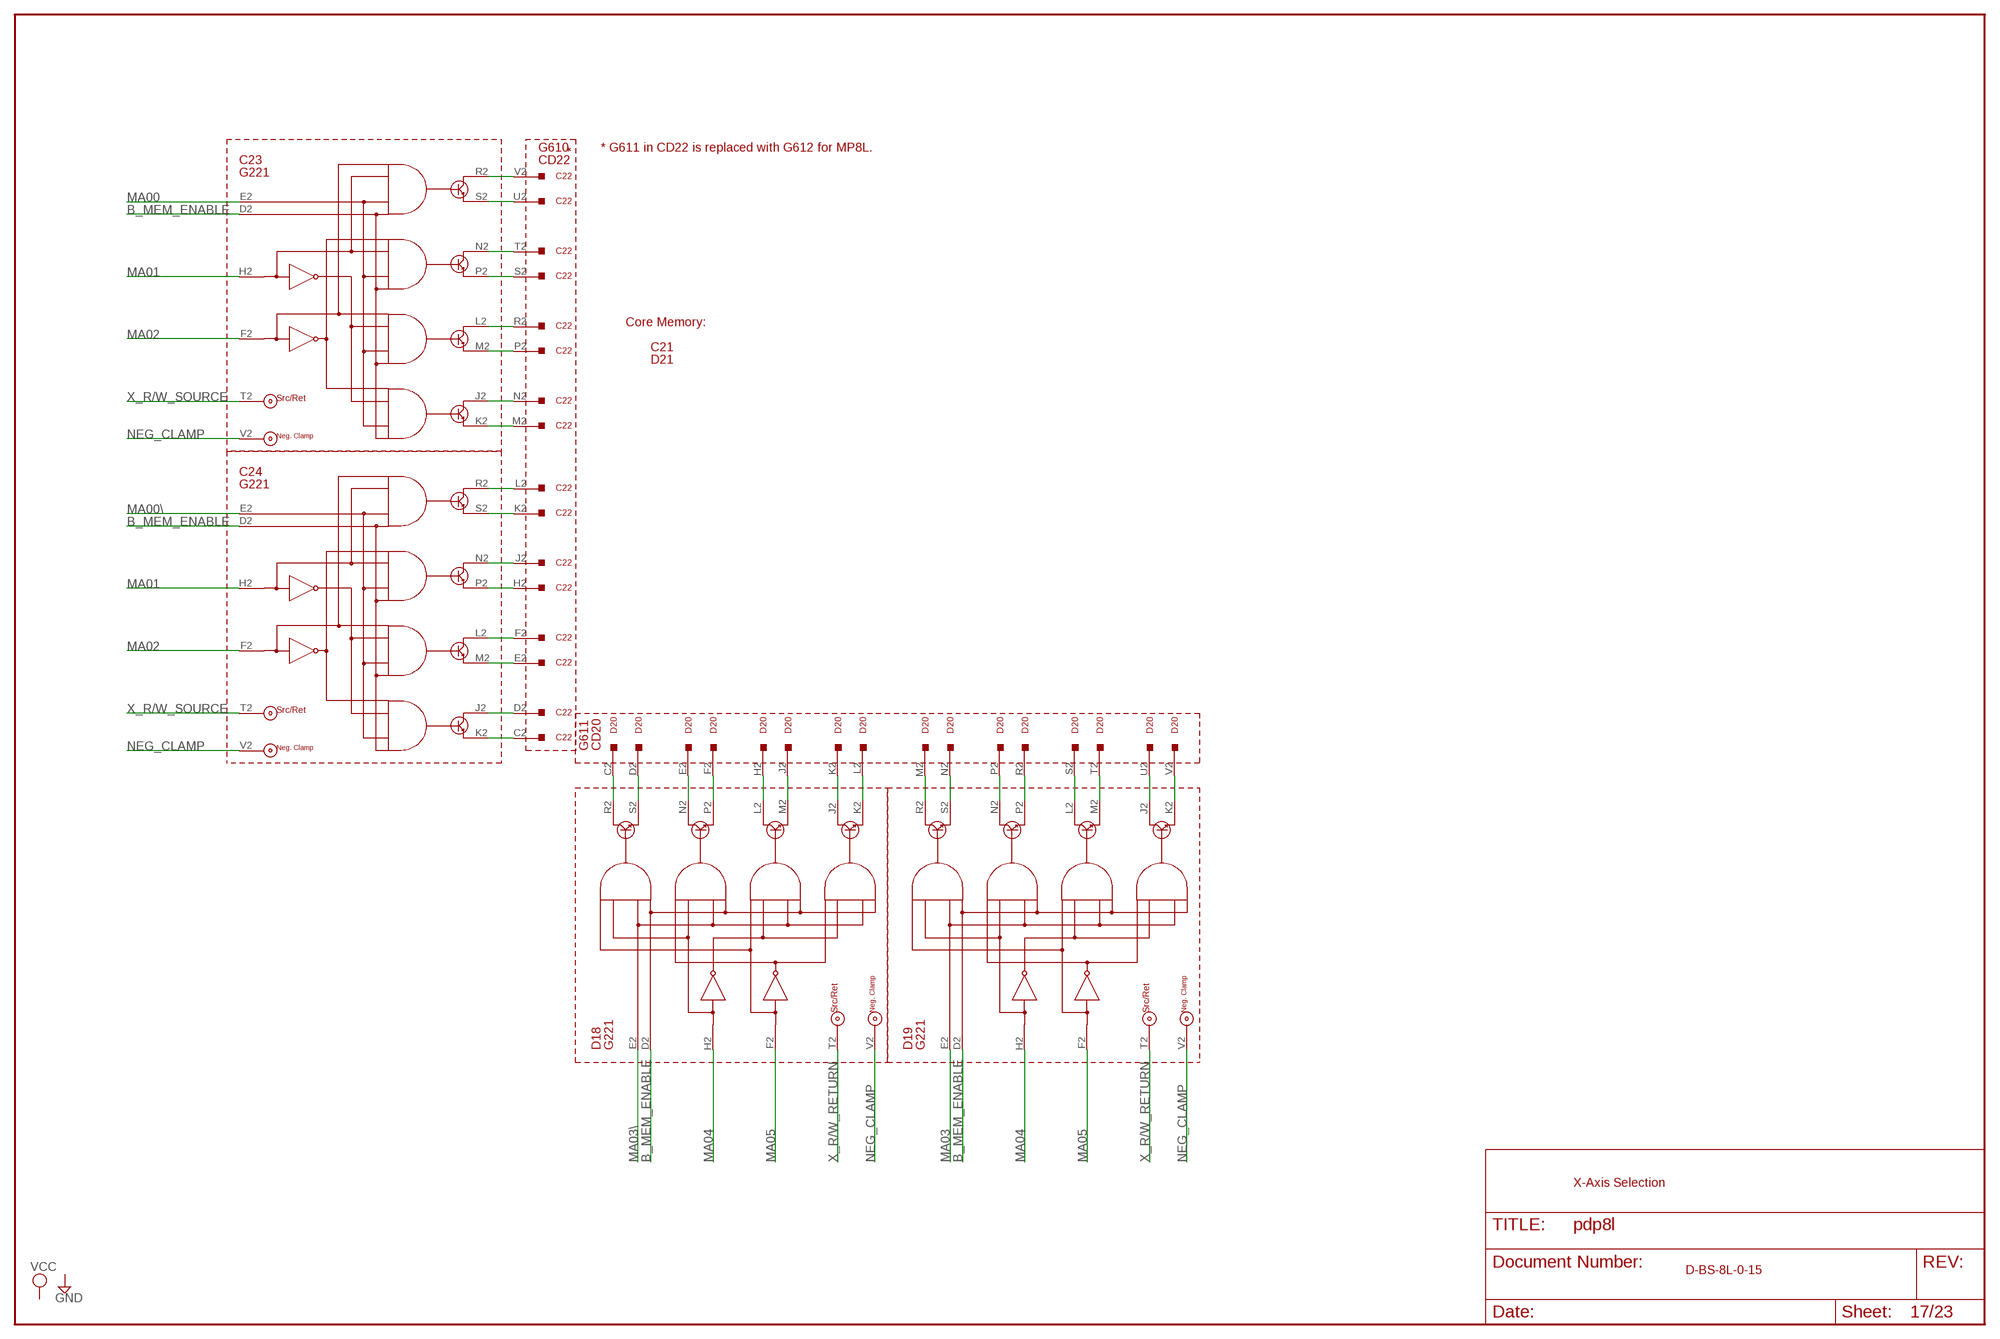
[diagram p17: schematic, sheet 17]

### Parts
C21  H807  [H807]
C22  G610A  W023  [H807]
C23  G221  [H807]
C24  G221  [H807]
D18  G221  [H807]
D19  G221  [H807]
D20  G611B  W023  [H807]
D21  H807  [H807]

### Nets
B_MEM_ENABLE: C23.D2 C24.D2 D18.D2 D19.D2 ; also sheet 15,16,18
MA00: C23.E2 ; also sheet 2,7
MA00\: C24.E2 ; also sheet 4,7,19
MA01: C23.H2 C24.H2 ; also sheet 2,7
MA02: C23.F2 C24.F2 ; also sheet 2,7
MA03: D19.E2 ; also sheet 2,7
MA03\: D18.E2 ; also sheet 4,7,19
MA04: D18.H2 D19.H2 ; also sheet 2,7
MA05: D18.F2 D19.F2 ; also sheet 7
N$342: C22.V2 C23.R2
N$343: C22.U2 C23.S2
N$344: C22.T2 C23.N2
N$345: C22.S2 C23.P2
N$346: C22.C2 C24.K2
N$347: C22.D2 C24.J2
N$348: C22.E2 C24.M2
N$349: C22.F2 C24.L2
N$350: C22.H2 C24.P2
N$351: C22.J2 C24.N2
N$352: C22.K2 C24.S2
N$353: C22.L2 C24.R2
N$354: C22.M2 C23.K2
N$355: C22.N2 C23.J2
N$356: C22.P2 C23.M2
N$357: C22.R2 C23.L2
N$358: D18.R2 D20.C2
N$359: D18.S2 D20.D2
N$360: D18.N2 D20.E2
N$361: D18.P2 D20.F2
N$362: D18.L2 D20.H2
N$363: D18.M2 D20.J2
N$364: D18.J2 D20.K2
N$365: D18.K2 D20.L2
N$366: D19.R2 D20.M2
N$367: D19.S2 D20.N2
N$368: D19.N2 D20.P2
N$369: D19.P2 D20.R2
N$370: D19.L2 D20.S2
N$371: D19.M2 D20.T2
N$372: D19.J2 D20.U2
N$373: D19.K2 D20.V2
NEG_CLAMP: C23.V2 C24.V2 D18.V2 D19.V2 ; also sheet 15,18
X_R/W_RETURN: D18.T2 D19.T2 ; also sheet 15
X_R/W_SOURCE: C23.T2 C24.T2 ; also sheet 15
Unconnected: C22.A2 C22.B2 D20.A2 D20.B2

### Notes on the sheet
- G610 | * | * G611 in CD22 is replaced with G612 for MP8L.
- CD22
- Core Memory:
- G611 | CD20
- X-Axis Selection
- D-BS-8L-0-15

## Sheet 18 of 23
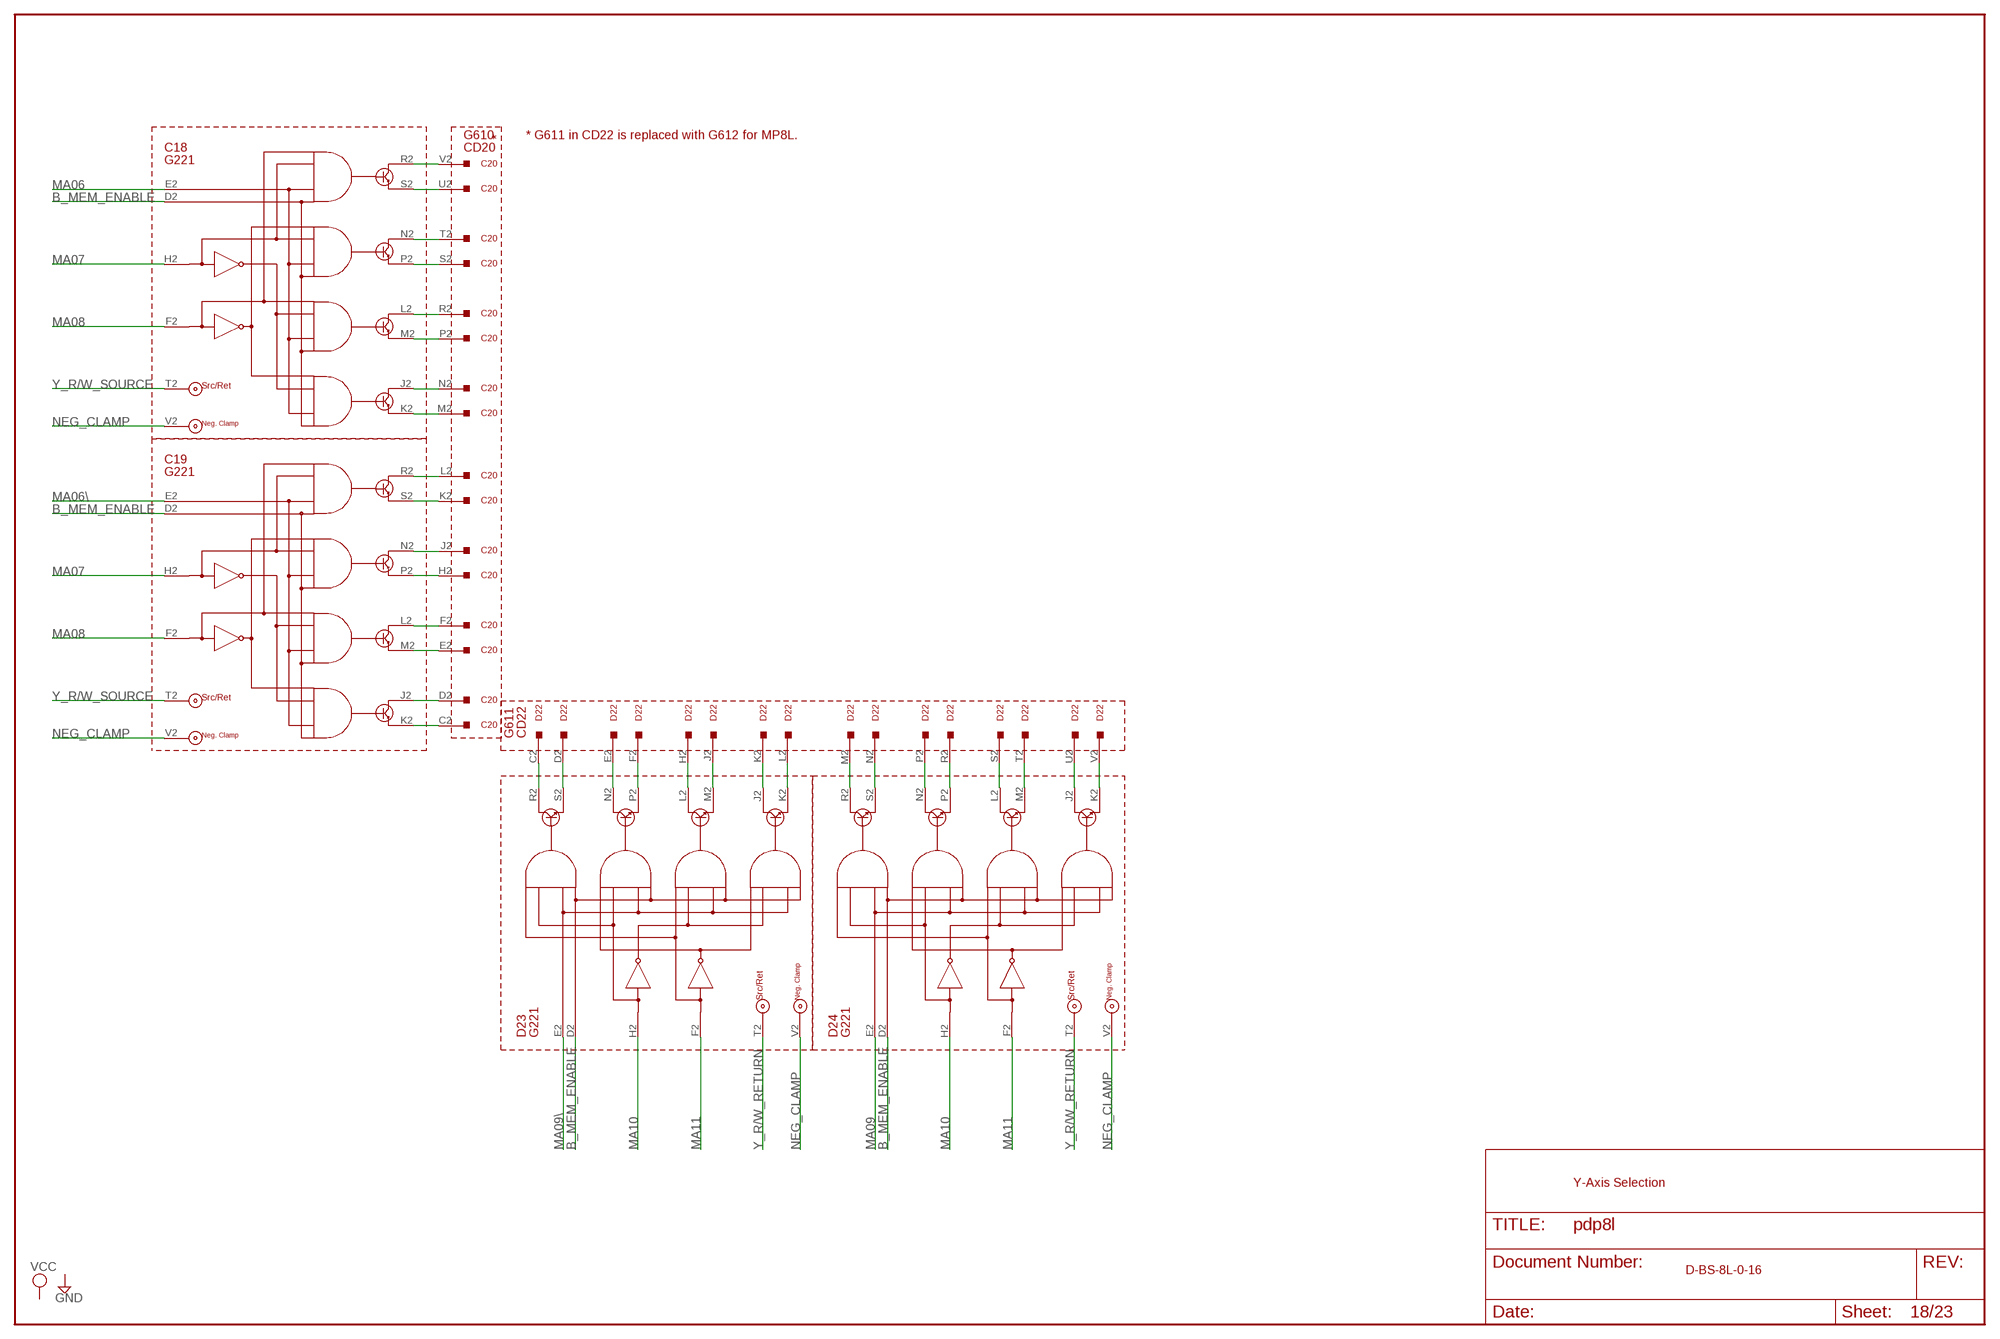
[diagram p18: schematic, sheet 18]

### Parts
C18  G221  [H807]
C19  G221  [H807]
C20  G610A  W023  [H807]
D22  G611B  W023  [H807]
D23  G221  [H807]
D24  G221  [H807]

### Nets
B_MEM_ENABLE: C18.D2 C19.D2 D23.D2 D24.D2 ; also sheet 15,16,17
MA06: C18.E2 ; also sheet 7
MA06\: C19.E2 ; also sheet 4,7,16,19
MA07: C18.H2 C19.H2 ; also sheet 7
MA08: C18.F2 C19.F2 ; also sheet 4,7
MA09: D24.E2 ; also sheet 7
MA09\: D23.E2 ; also sheet 7,19
MA10: D23.H2 D24.H2 ; also sheet 7
MA11: D23.F2 D24.F2 ; also sheet 7
N$374: C18.R2 C20.V2
N$375: C18.S2 C20.U2
N$376: C18.N2 C20.T2
N$377: C18.P2 C20.S2
N$378: C18.L2 C20.R2
N$379: C18.M2 C20.P2
N$380: C18.J2 C20.N2
N$381: C18.K2 C20.M2
N$382: C19.K2 C20.C2
N$383: C19.J2 C20.D2
N$384: C19.M2 C20.E2
N$385: C19.L2 C20.F2
N$386: C19.P2 C20.H2
N$387: C19.N2 C20.J2
N$388: C19.S2 C20.K2
N$389: C19.R2 C20.L2
N$390: D22.C2 D23.R2
N$391: D22.D2 D23.S2
N$392: D22.E2 D23.N2
N$393: D22.F2 D23.P2
N$394: D22.H2 D23.L2
N$395: D22.J2 D23.M2
N$396: D22.K2 D23.J2
N$397: D22.L2 D23.K2
N$398: D22.M2 D24.R2
N$399: D22.N2 D24.S2
N$400: D22.P2 D24.N2
N$401: D22.R2 D24.P2
N$402: D22.S2 D24.L2
N$403: D22.T2 D24.M2
N$404: D22.U2 D24.J2
N$405: D22.V2 D24.K2
NEG_CLAMP: C18.V2 C19.V2 D23.V2 D24.V2 ; also sheet 15,17
Y_R/W_RETURN: D23.T2 D24.T2 ; also sheet 15
Y_R/W_SOURCE: C18.T2 C19.T2 ; also sheet 15
Unconnected: C20.A2 C20.B2 D22.A2 D22.B2

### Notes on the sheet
- G610 | * | * G611 in CD22 is replaced with G612 for MP8L.
- CD20
- G611 | CD22
- Y-Axis Selection
- D-BS-8L-0-16

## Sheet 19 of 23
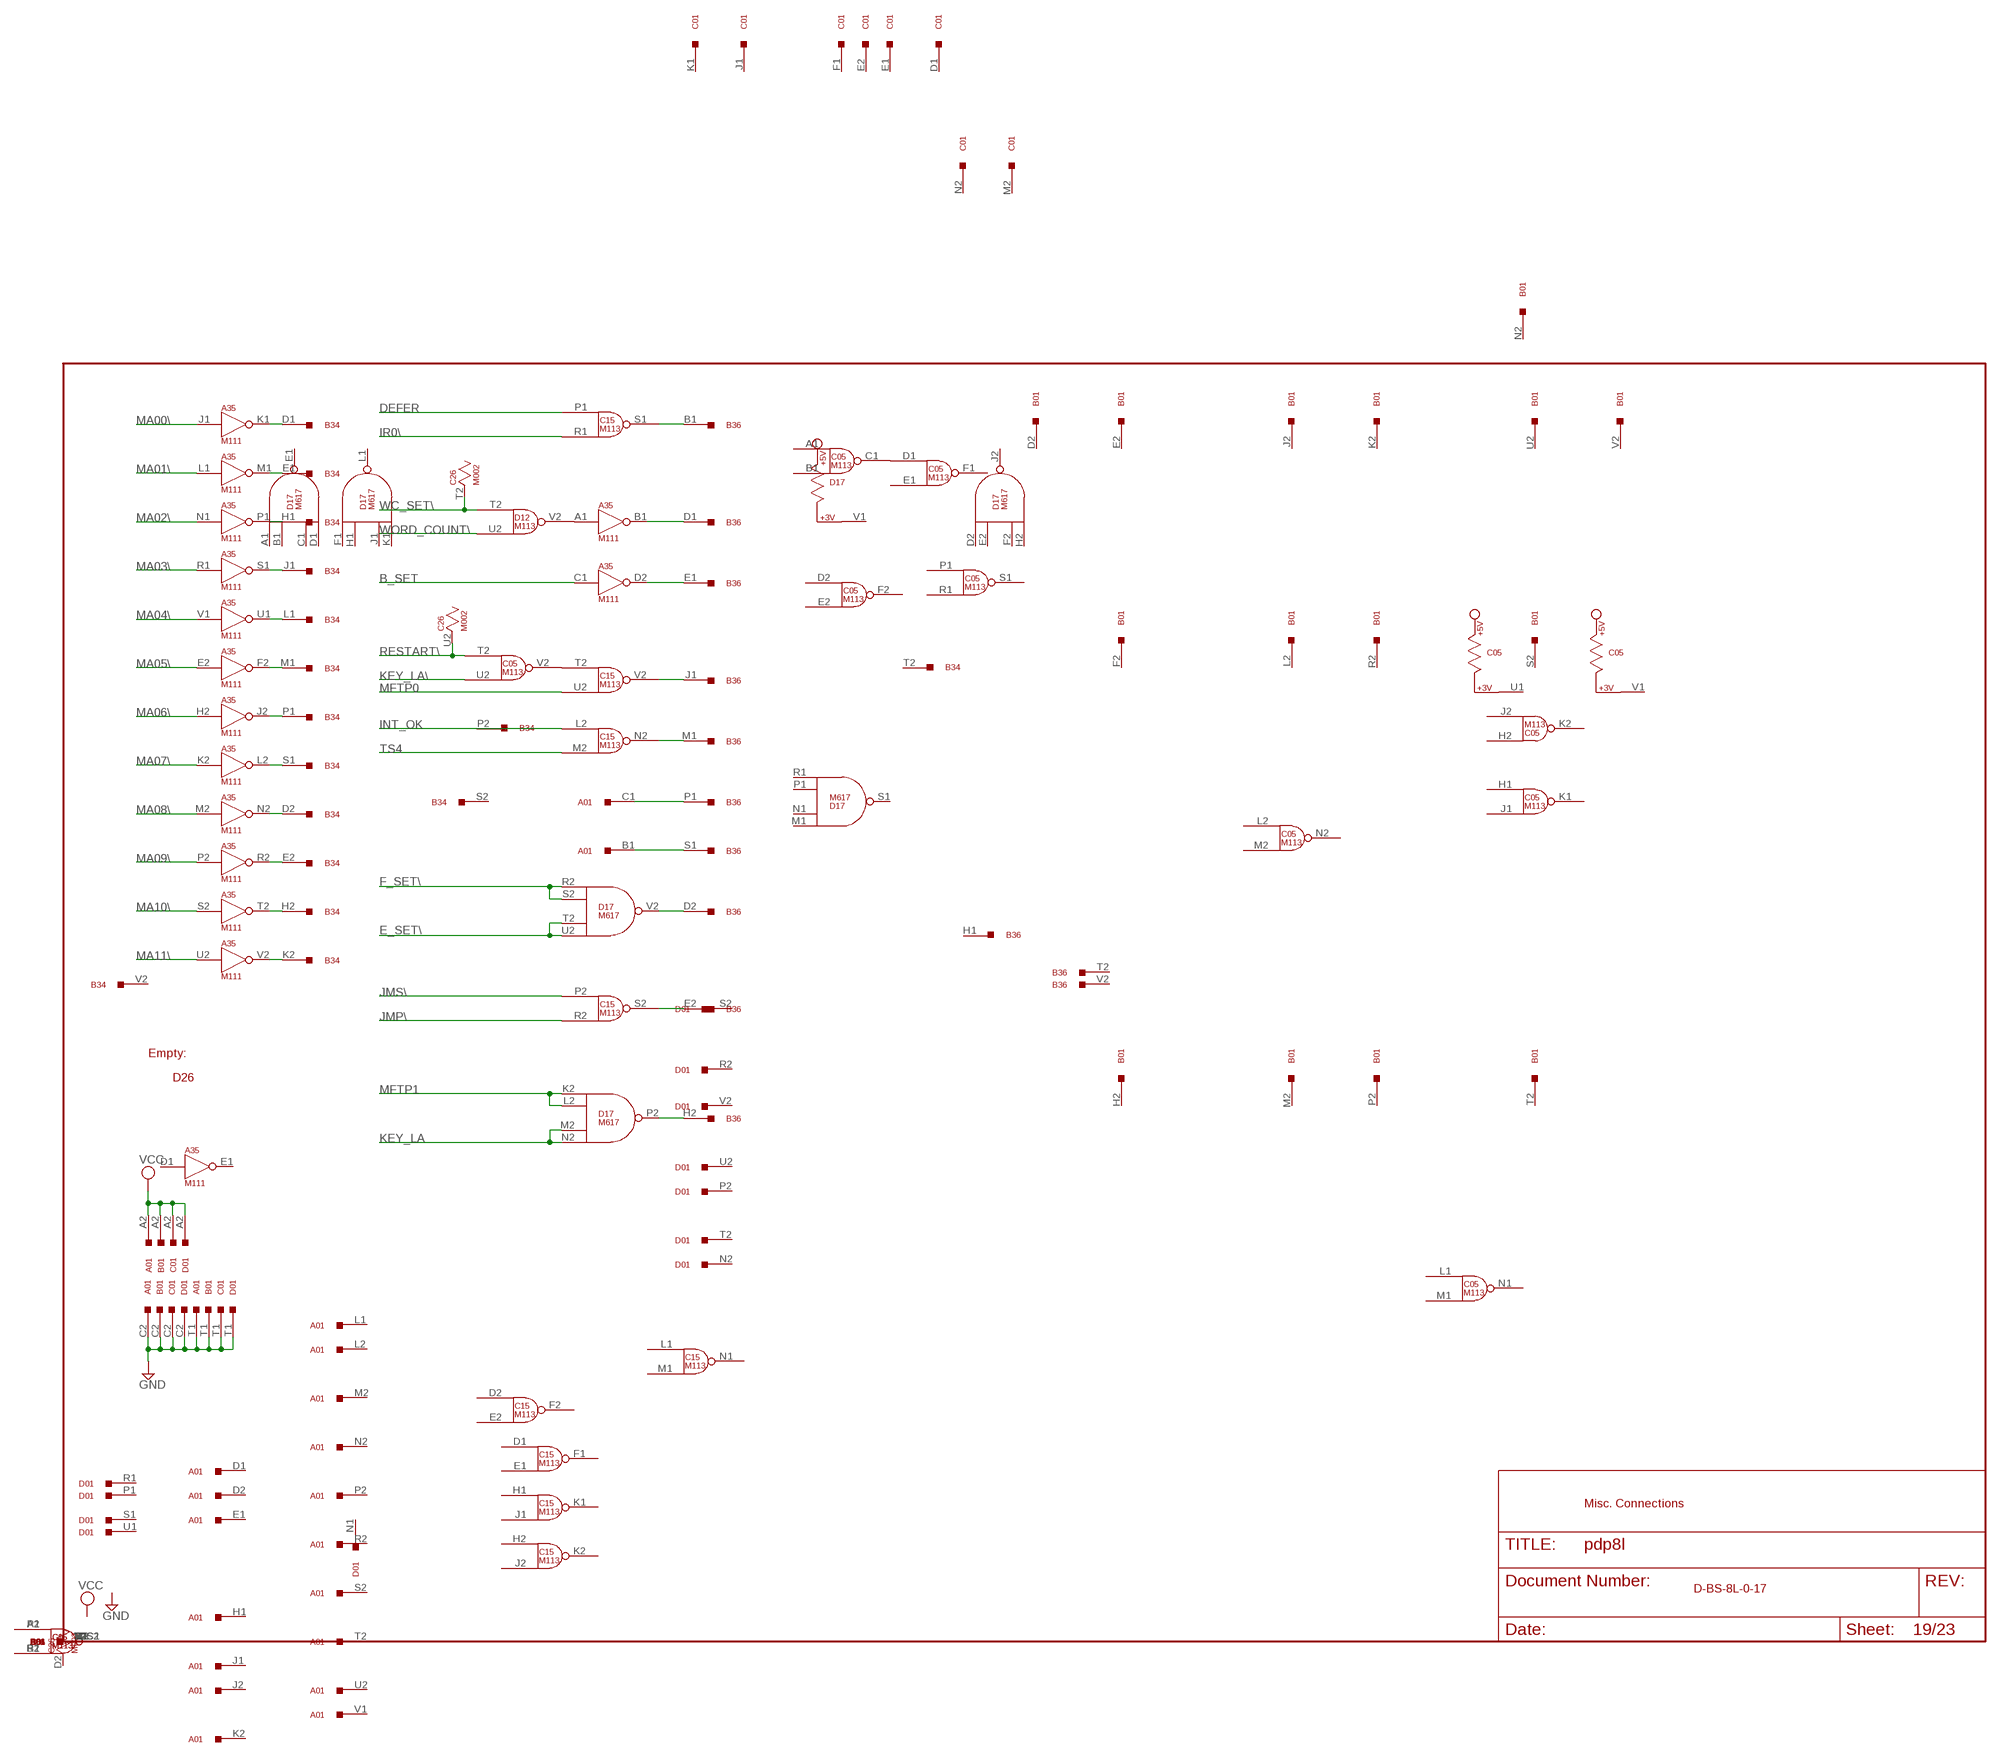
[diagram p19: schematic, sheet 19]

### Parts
D26  H807  [H807]

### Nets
B_SET: A35.C1(D2:IN) ; also sheet 2
DEFER: C15.P1(S1:IN1) ; also sheet 2,3,4,5
E_SET\: D17.T2(V2:IN3) D17.U2(V2:IN4) ; also sheet 2,3
F_SET\: D17.R2(V2:IN1) D17.S2(V2:IN2) ; also sheet 2
GND [Supply]: A01.C2 A01.T1 B01.C2 B01.T1 C01.C2 C01.T1 D01.C2 D01.T1 ; also sheet 1,3,8,9,10,11,12,13,14,15,16,20,21,23
INT_OK: C15.L2(N2:IN1) ; also sheet 2,6
IR0\: C15.R1(S1:IN2) ; also sheet 2
JMP\: C15.R2(S2:IN2) ; also sheet 2,3
JMS\: C15.P2(S2:IN1) ; also sheet 2
KEY_LA: D17.M2(P2:IN3) D17.N2(P2:IN4) ; also sheet 1,3
KEY_LA\: C05.U2(V2:IN2) ; also sheet 1
MA00\: A35.J1(K1:IN) ; also sheet 4,7,17
MA01\: A35.L1(M1:IN) ; also sheet 4,7
MA02\: A35.N1(P1:IN) ; also sheet 4,7
MA03\: A35.R1(S1:IN) ; also sheet 4,7,17
MA04\: A35.V1(U1:IN) ; also sheet 4,7,16
MA05\: A35.E2(F2:IN) ; also sheet 4,7,16
MA06\: A35.H2(J2:IN) ; also sheet 4,7,16,18
MA07\: A35.K2(L2:IN) ; also sheet 4,7,16
MA08\: A35.M2(N2:IN) ; also sheet 7
MA09\: A35.P2(R2:IN) ; also sheet 7,18
MA10\: A35.S2(T2:IN) ; also sheet 7
MA11\: A35.U2(V2:IN) ; also sheet 7
MFTP0: C15.U2(V2:IN2) ; also sheet 1
MFTP1: D17.K2(P2:IN1) D17.L2(P2:IN2) ; also sheet 1,5
N$318: A35.K1(K1:OUT) B34.D1
N$319: A35.M1(M1:OUT) B34.E1
N$320: A35.P1(P1:OUT) B34.H1
N$321: A35.S1(S1:OUT) B34.J1
N$322: A35.U1(U1:OUT) B34.L1
N$323: A35.F2(F2:OUT) B34.M1
N$324: A35.J2(J2:OUT) B34.P1
N$325: A35.L2(L2:OUT) B34.S1
N$326: A35.R2(R2:OUT) B34.E2
N$327: A35.N2(N2:OUT) B34.D2
N$328: A35.T2(T2:OUT) B34.H2
N$329: A35.V2(V2:OUT) B34.K2
N$330: B36.H2 D17.P2(P2:OUT)
N$331: B36.E2 C15.S2(S2:OUT)
N$332: B36.D2 D17.V2(V2:OUT)
N$333: A01.B1 B36.S1
N$334: A01.C1 B36.P1
N$335: B36.M1 C15.N2(N2:OUT)
N$336: B36.J1 C15.V2(V2:OUT)
N$337: A35.D2(D2:OUT) B36.E1
N$338: A35.B1(B1:OUT) B36.D1
N$339: B36.B1 C15.S1(S1:OUT)
N$340: A35.A1(B1:IN) D12.V2(V2:OUT)
N$341: C05.V2(V2:OUT) C15.T2(V2:IN1)
RESTART\: C05.T2(V2:IN1) C26.U2 ; also sheet 1,3,20
TS4: C15.M2(N2:IN2) ; also sheet 1,3
VCC [Supply]: A01.A2 B01.A2 C01.A2 D01.A2 ; also sheet 13,14,15,20
WC_SET\: C26.T2 D12.T2(V2:IN1) ; also sheet 2
WORD_COUNT\: D12.U2(V2:IN2) ; also sheet 2,4,6

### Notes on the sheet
- Empty:
- Misc. Connections
- D-BS-8L-0-17

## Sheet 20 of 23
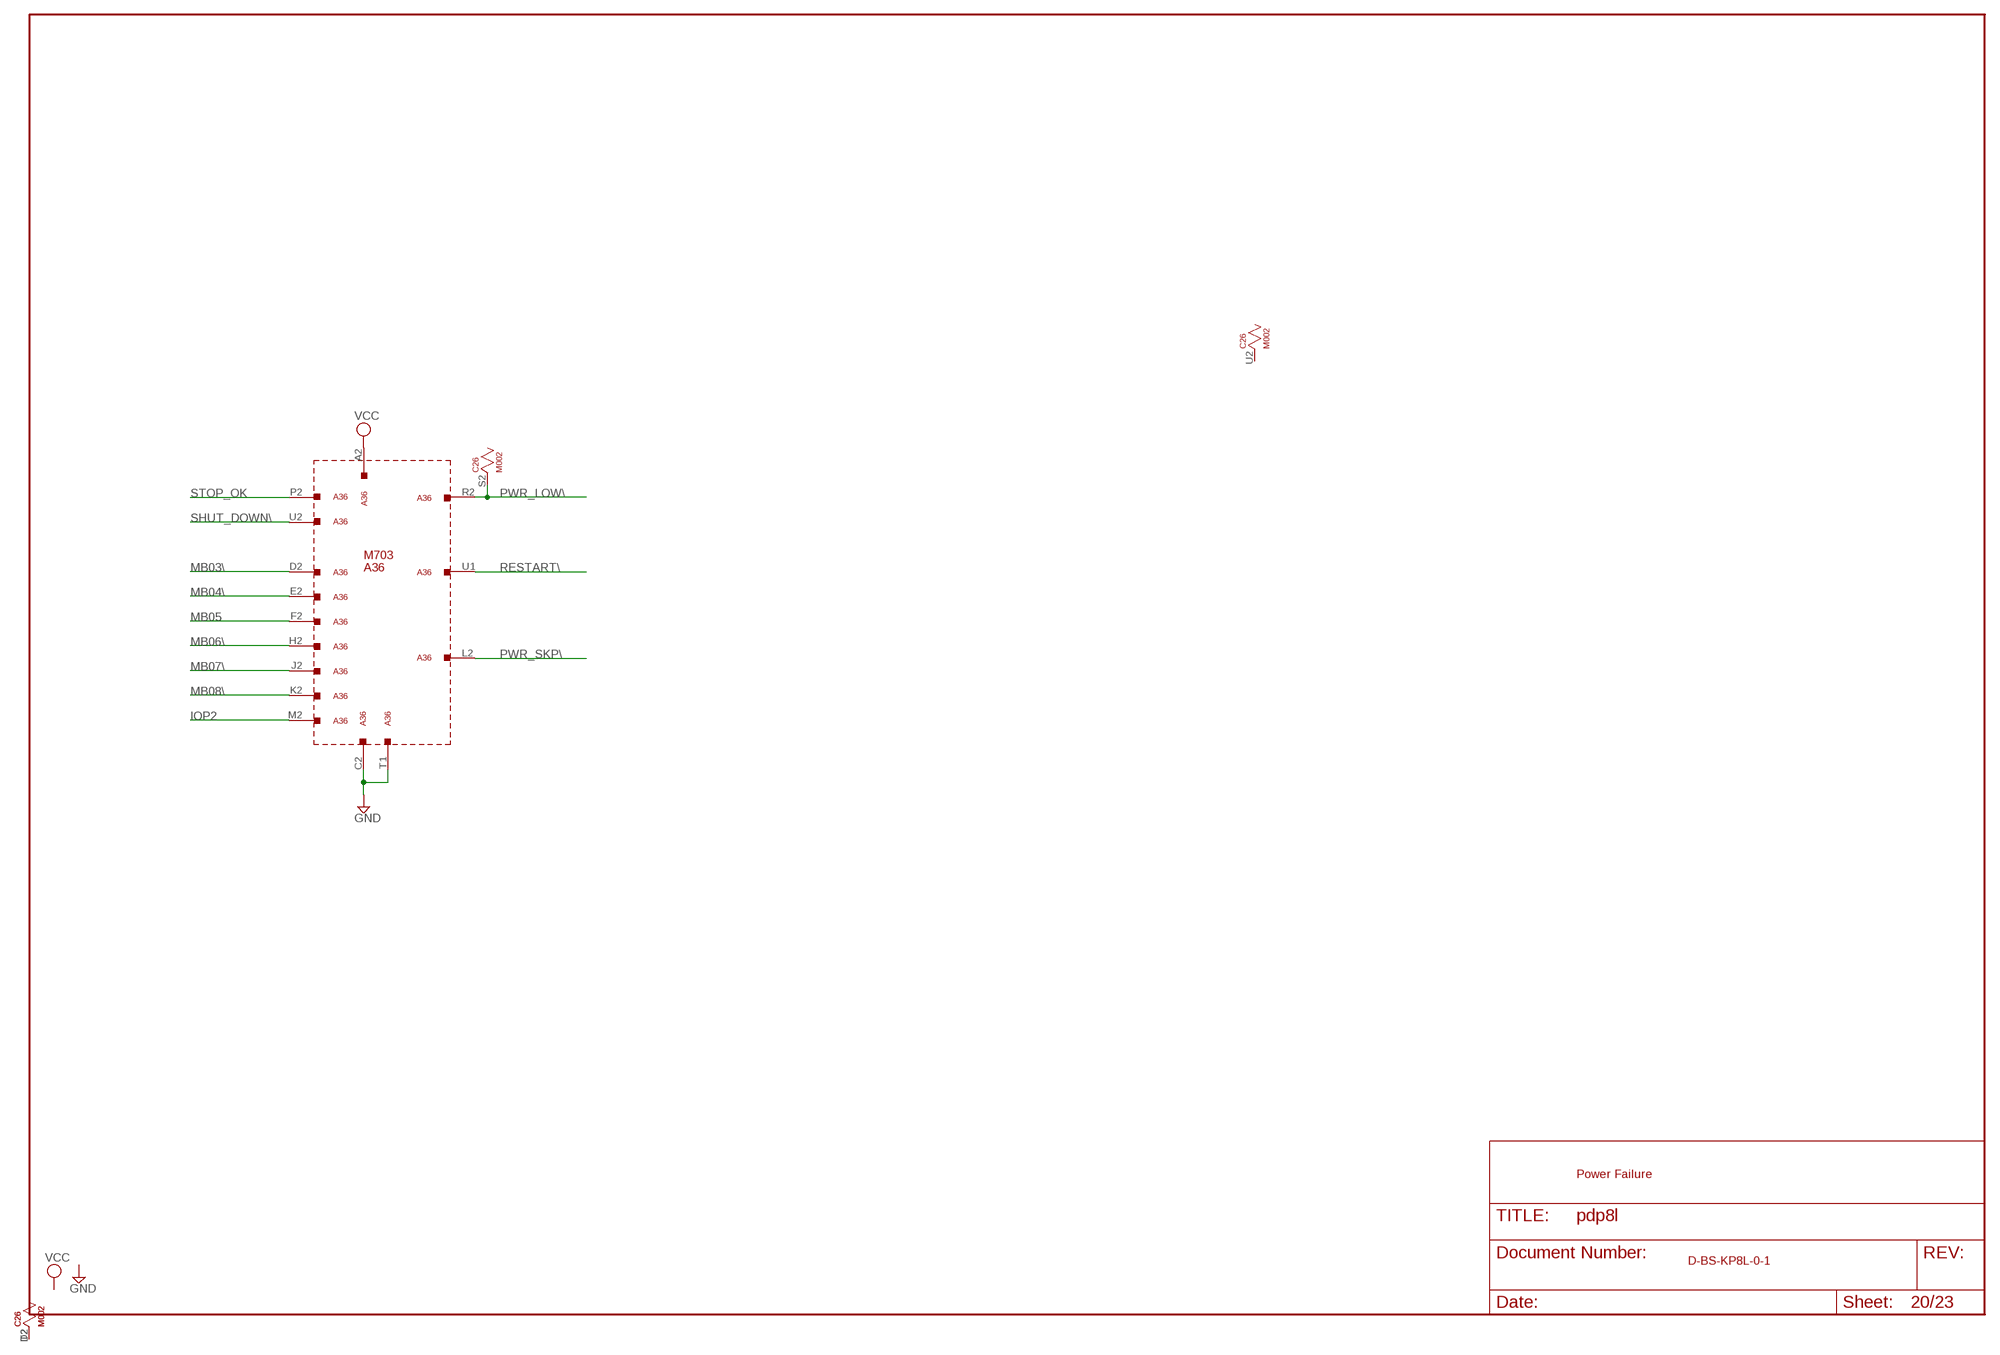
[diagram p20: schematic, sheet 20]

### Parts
A36  M916  [H807]

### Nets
GND [Supply]: A36.C2 A36.T1 ; also sheet 1,3,8,9,10,11,12,13,14,15,16,19,21,23
IOP2: A36.M2 ; also sheet 1,13,14,21,22
MB03\: A36.D2 ; also sheet 2,3,6,7,12,13,14,16,21,22,23
MB04\: A36.E2 ; also sheet 3,6,7,12,13,14,21,22,23
MB05: A36.F2 ; also sheet 3,5,7,12,23
MB06\: A36.H2 ; also sheet 3,6,7,12,13,21,22,23
MB07\: A36.J2 ; also sheet 3,6,7,12,14,22,23
MB08\: A36.K2 ; also sheet 4,5,6,7,12,14,16,21,23
PWR_LOW\: A36.R2 C26.S2 ; also sheet 12
PWR_SKP\: A36.L2 ; also sheet 12
RESTART\: A36.U1 ; also sheet 1,3,19
SHUT_DOWN\: A36.U2 ; also sheet 15
STOP_OK: A36.P2 ; also sheet 1,15
VCC [Supply]: A36.A2 ; also sheet 13,14,15,19
Unconnected: A36.A1 A36.B1 A36.B2 A36.C1 A36.D1 A36.E1 A36.F1 A36.H1 A36.J1 A36.K1 A36.L1 A36.M1 A36.N1 A36.N2 A36.P1 A36.R1 A36.S1 A36.S2 A36.T2 A36.V1 A36.V2

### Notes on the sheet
- M703
- A36
- Power Failure
- D-BS-KP8L-0-1

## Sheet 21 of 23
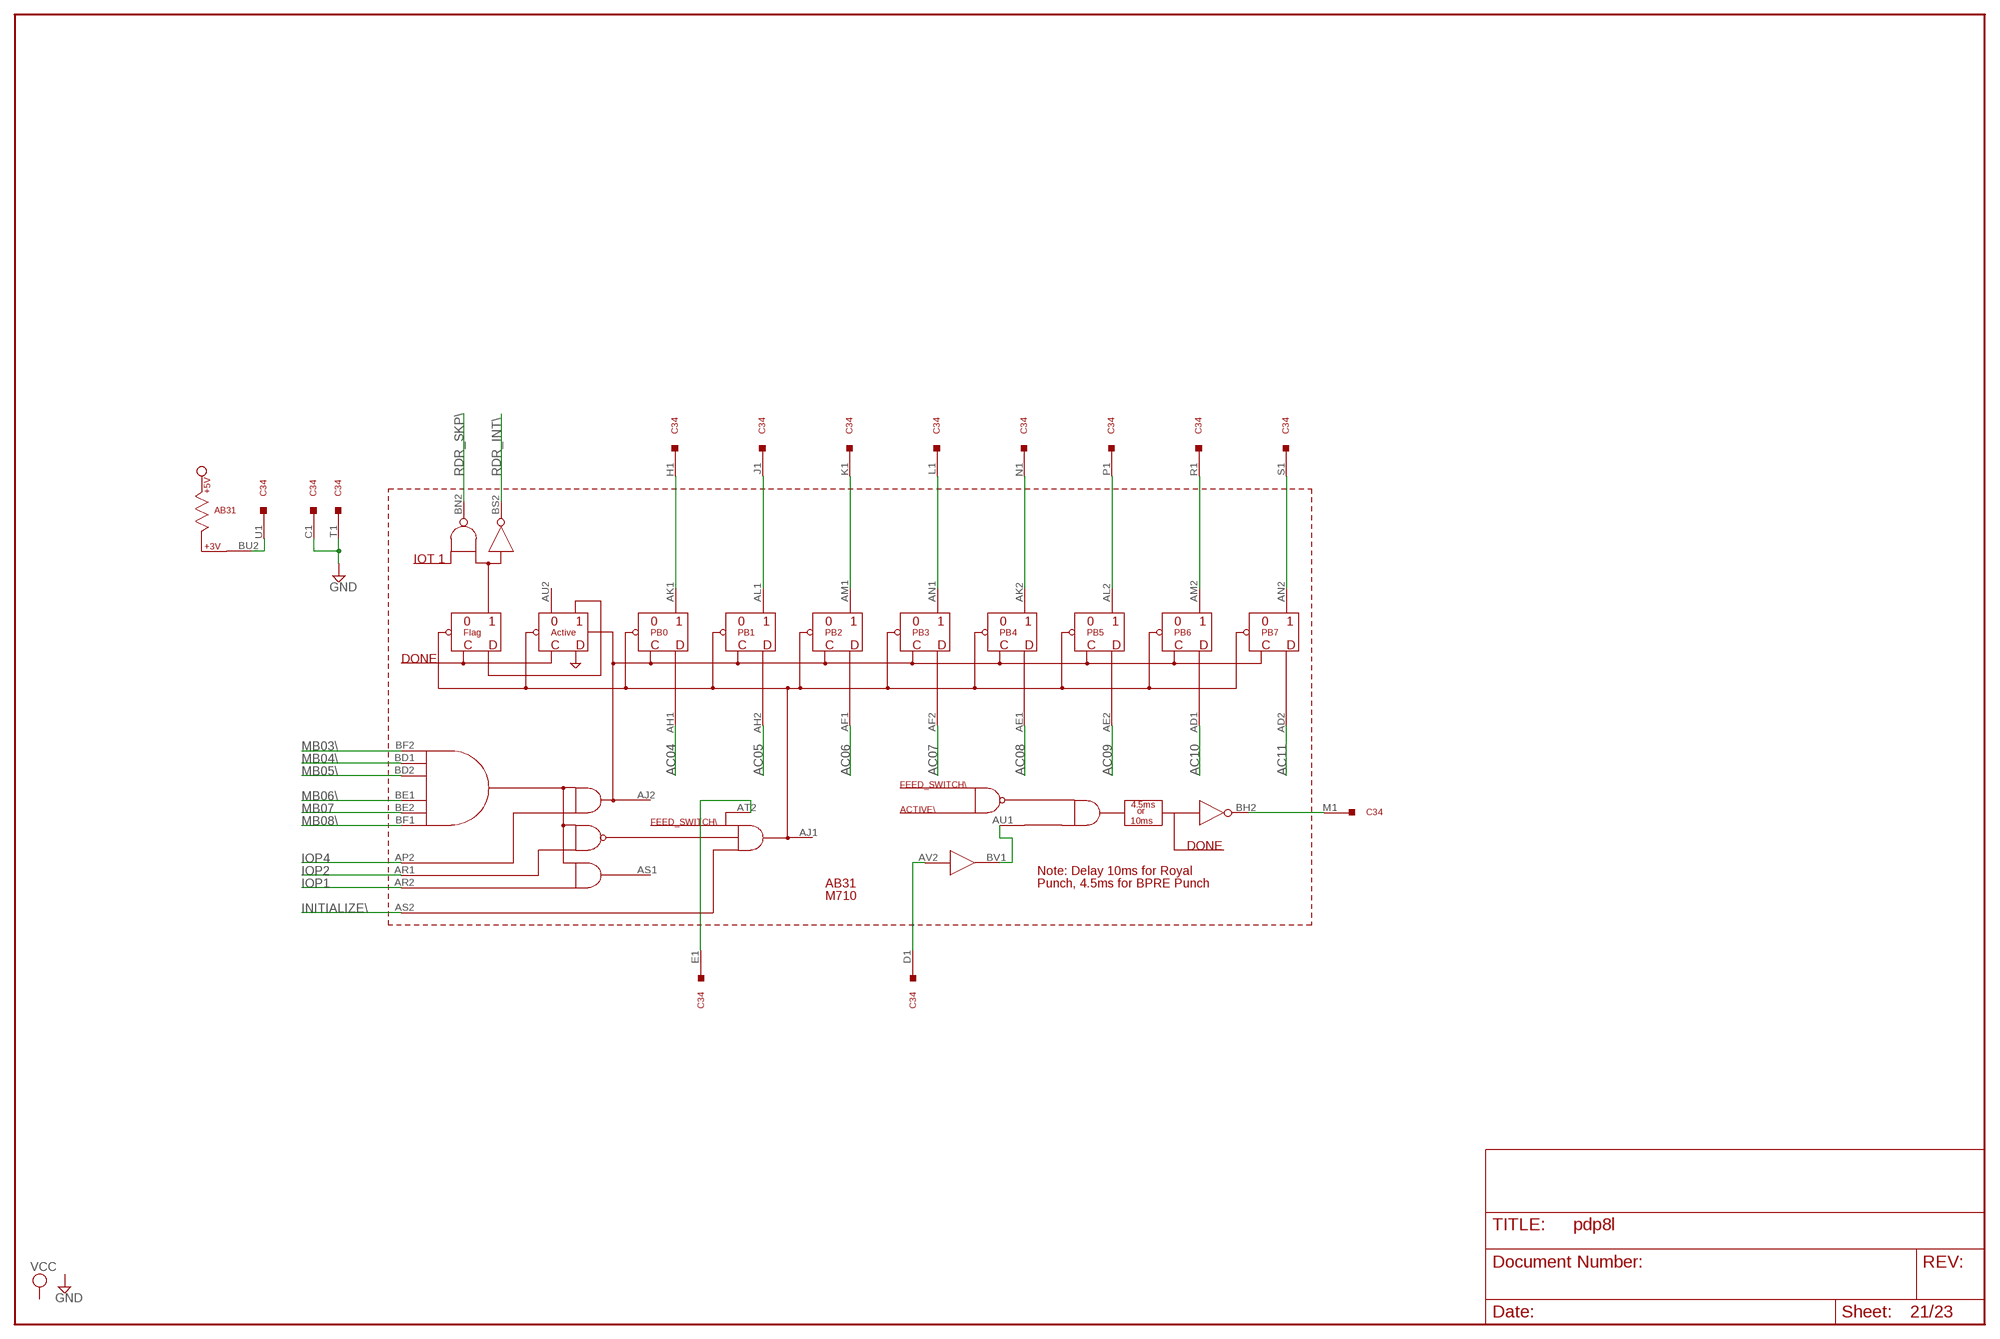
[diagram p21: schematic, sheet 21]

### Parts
AB31  M710  [H807-2]
C34  M916  [H807]

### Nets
AC04: AB31.AH1 ; also sheet 7,12,14
AC05: AB31.AH2 ; also sheet 7,12,14
AC06: AB31.AF1 ; also sheet 7,12,14
AC07: AB31.AF2 ; also sheet 7,12,14
AC08: AB31.AE1 ; also sheet 7,12,14
AC09: AB31.AE2 ; also sheet 7,12,14
AC10: AB31.AD1 ; also sheet 7,12,14
AC11: AB31.AD2 ; also sheet 7,12,14
GND [Supply]: C34.C1 C34.T1 ; also sheet 1,3,8,9,10,11,12,13,14,15,16,19,20,23
INITIALIZE\: AB31.AS2 ; also sheet 1,12,22
IOP1: AB31.AR2 ; also sheet 1,13,14,22,23
IOP2: AB31.AR1 ; also sheet 1,13,14,20,22
IOP4: AB31.AP2 ; also sheet 1,13,14,22,23
MB03\: AB31.BF2 ; also sheet 2,3,6,7,12,13,14,16,20,22,23
MB04\: AB31.BD1 ; also sheet 3,6,7,12,13,14,20,22,23
MB05\: AB31.BD2 ; also sheet 3,6,7,12,13,14,22,23
MB06\: AB31.BE1 ; also sheet 3,6,7,12,13,20,22,23
MB07: AB31.BE2 ; also sheet 3,5,7,12,13,23
MB08\: AB31.BF1 ; also sheet 4,5,6,7,12,14,16,20,23
N$17: AB31.AU1 AB31.BV1
N$18: AB31.AK1 C34.H1
N$33: AB31.AL1 C34.J1
N$34: AB31.AM1 C34.K1
N$35: AB31.AN1 C34.L1
N$107: AB31.AK2 C34.N1
N$202: AB31.AL2 C34.P1
N$220: AB31.AM2 C34.R1
N$254: AB31.AN2 C34.S1
N$255: AB31.BH2 C34.M1
N$256: AB31.AT2 C34.E1
N$257: AB31.AV2 C34.D1
N$258: AB31.BU2 C34.U1
RDR_INT\: AB31.BS2 ; also sheet 12,22
RDR_SKP\: AB31.BN2 ; also sheet 12,22
Unconnected: AB31.AJ1 AB31.AJ2 AB31.AS1 AB31.AU2 C34.A1 C34.A2 C34.B1 C34.C2 C34.F1 C34.V1

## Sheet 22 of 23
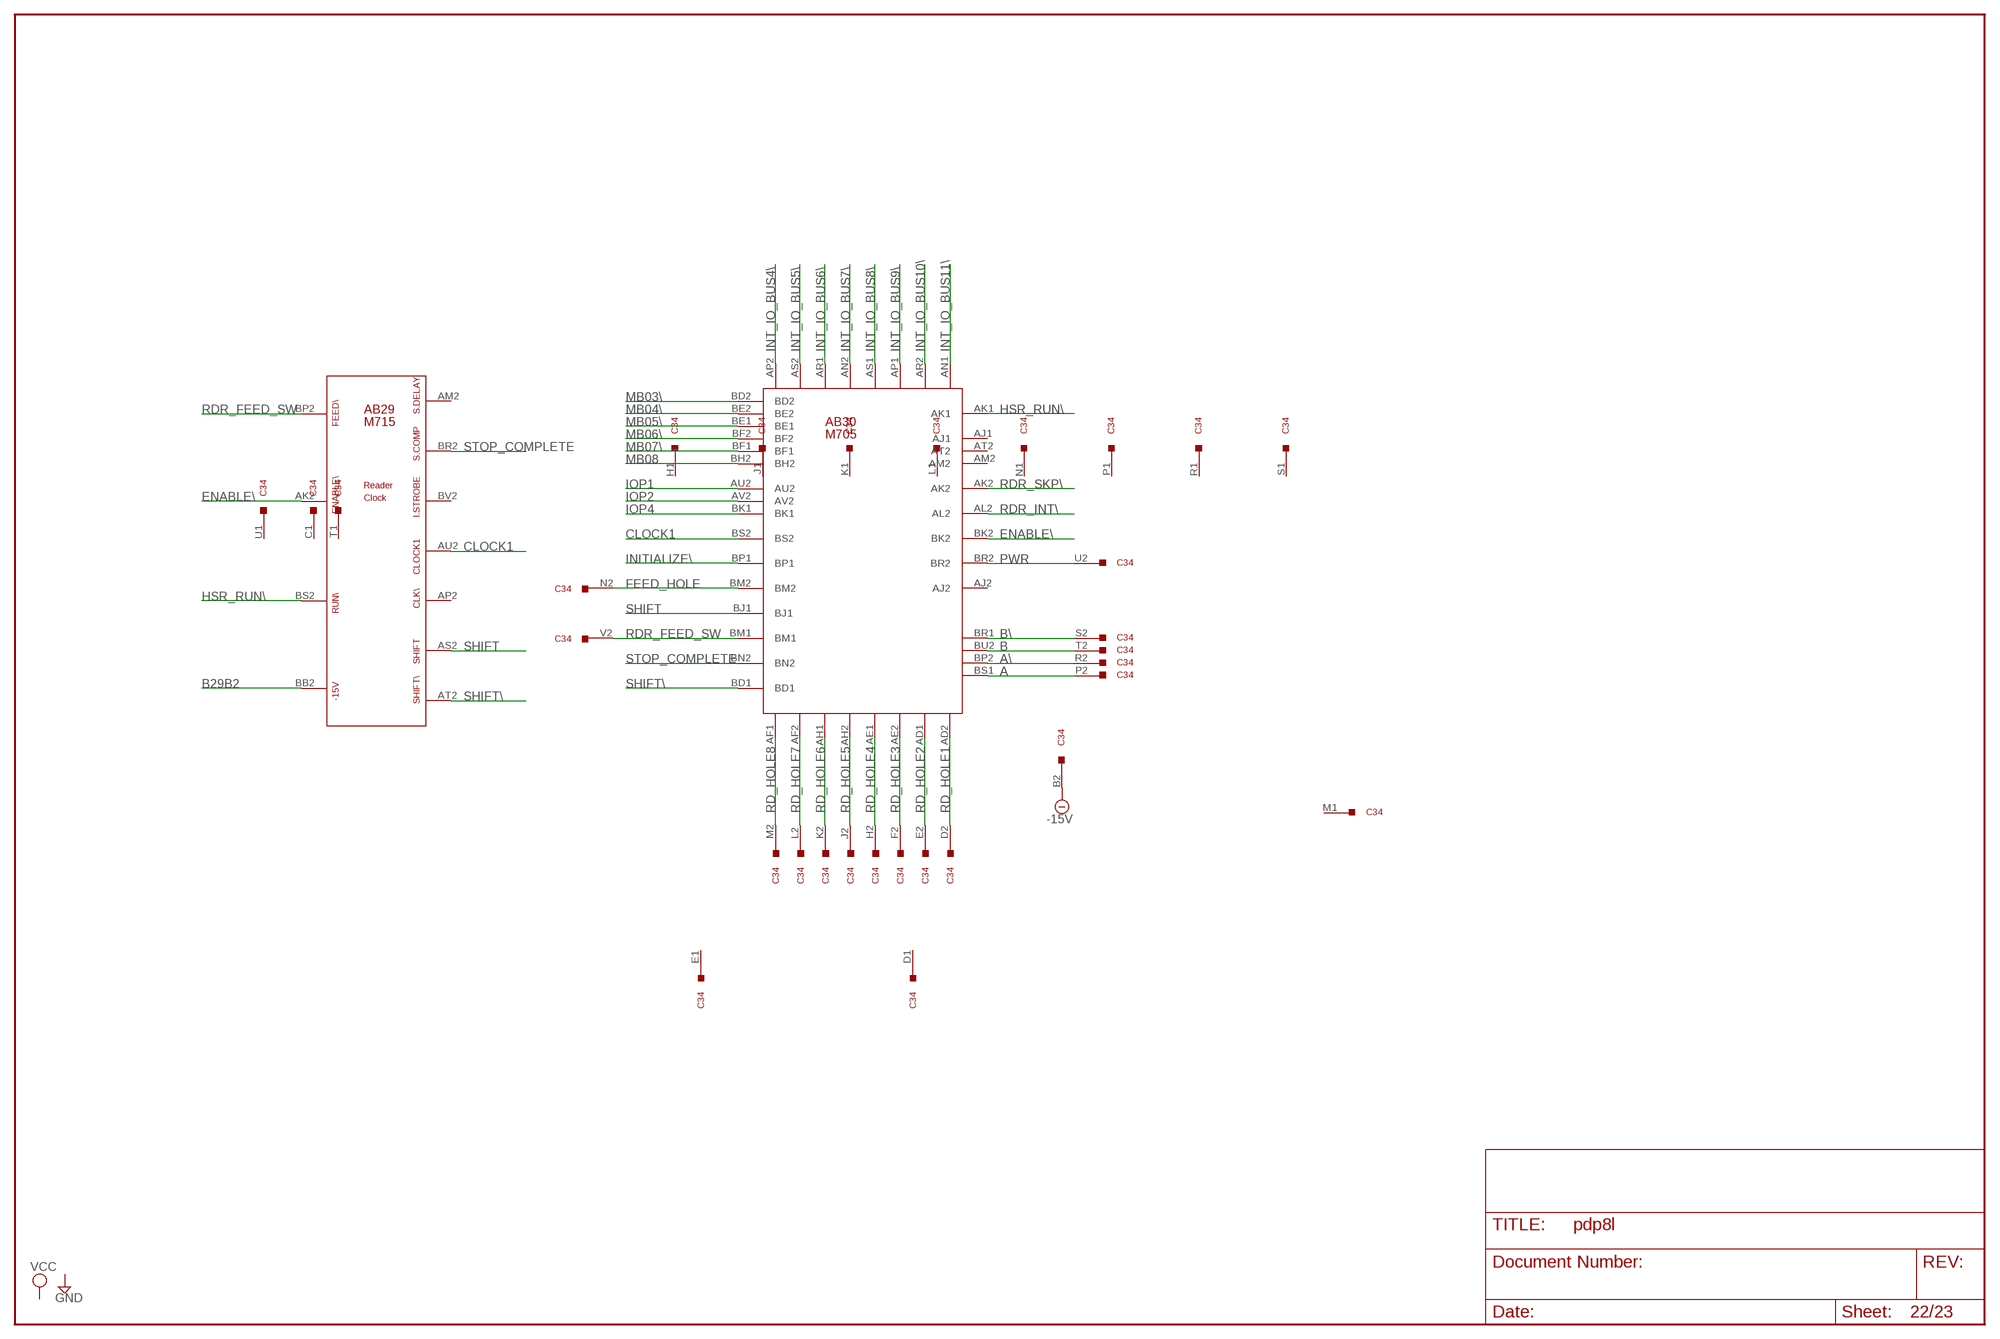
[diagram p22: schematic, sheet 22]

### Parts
AB29  M715  [H807-2]
AB30  M705  [H807-2]

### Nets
-15V [Supply]: C34.B2 ; also sheet 13
A: AB30.BS1 C34.P2
A\: AB30.BP2 C34.R2
B: AB30.BU2 C34.T2
B29B2 [Supply]: AB29.BB2(BB) ; also sheet 15
B\: AB30.BR1 C34.S2
CLOCK1: AB29.AU2(AU) AB30.BS2
ENABLE\: AB29.AK2(AK) AB30.BK2
FEED_HOLE: AB30.BM2 C34.N2
HSR_RUN\: AB29.BS2(BS) AB30.AK1
INITIALIZE\: AB30.BP1 ; also sheet 1,12,21
INT_IO_BUS4\: AB30.AP2 ; also sheet 12
INT_IO_BUS5\: AB30.AS2 ; also sheet 12
INT_IO_BUS6\: AB30.AR1 ; also sheet 12
INT_IO_BUS7\: AB30.AN2 ; also sheet 12
INT_IO_BUS8\: AB30.AS1 ; also sheet 12
INT_IO_BUS9\: AB30.AP1 ; also sheet 12
INT_IO_BUS10\: AB30.AR2 ; also sheet 12
INT_IO_BUS11\: AB30.AN1 ; also sheet 12
IOP1: AB30.AU2 ; also sheet 1,13,14,21,23
IOP2: AB30.AV2 ; also sheet 1,13,14,20,21
IOP4: AB30.BK1 ; also sheet 1,13,14,21,23
MB03\: AB30.BD2 ; also sheet 2,3,6,7,12,13,14,16,20,21,23
MB04\: AB30.BE2 ; also sheet 3,6,7,12,13,14,20,21,23
MB05\: AB30.BE1 ; also sheet 3,6,7,12,13,14,21,23
MB06\: AB30.BF2 ; also sheet 3,6,7,12,13,20,21,23
MB07\: AB30.BF1 ; also sheet 3,6,7,12,14,20,23
MB08: AB30.BH2 ; also sheet 4,5,7,12,13,23
PWR: AB30.BR2 C34.U2
RD_HOLE1: AB30.AD2 C34.D2
RD_HOLE2: AB30.AD1 C34.E2
RD_HOLE3: AB30.AE2 C34.F2
RD_HOLE4: AB30.AE1 C34.H2
RD_HOLE5: AB30.AH2 C34.J2
RD_HOLE6: AB30.AH1 C34.K2
RD_HOLE7: AB30.AF2 C34.L2
RD_HOLE8: AB30.AF1 C34.M2
RDR_FEED_SW: AB29.BP2(BP) AB30.BM1 C34.V2
RDR_INT\: AB30.AL2 ; also sheet 12,21
RDR_SKP\: AB30.AK2 ; also sheet 12,21
SHIFT: AB29.AS2(AS) AB30.BJ1
SHIFT\: AB29.AT2(AT) AB30.BD1
STOP_COMPLETE: AB29.BR2(BR) AB30.BN2
Unconnected: AB29.AM2(AM) AB29.AP2(AP) AB29.BV2(BV) AB30.AJ1 AB30.AJ2 AB30.AM2 AB30.AT2

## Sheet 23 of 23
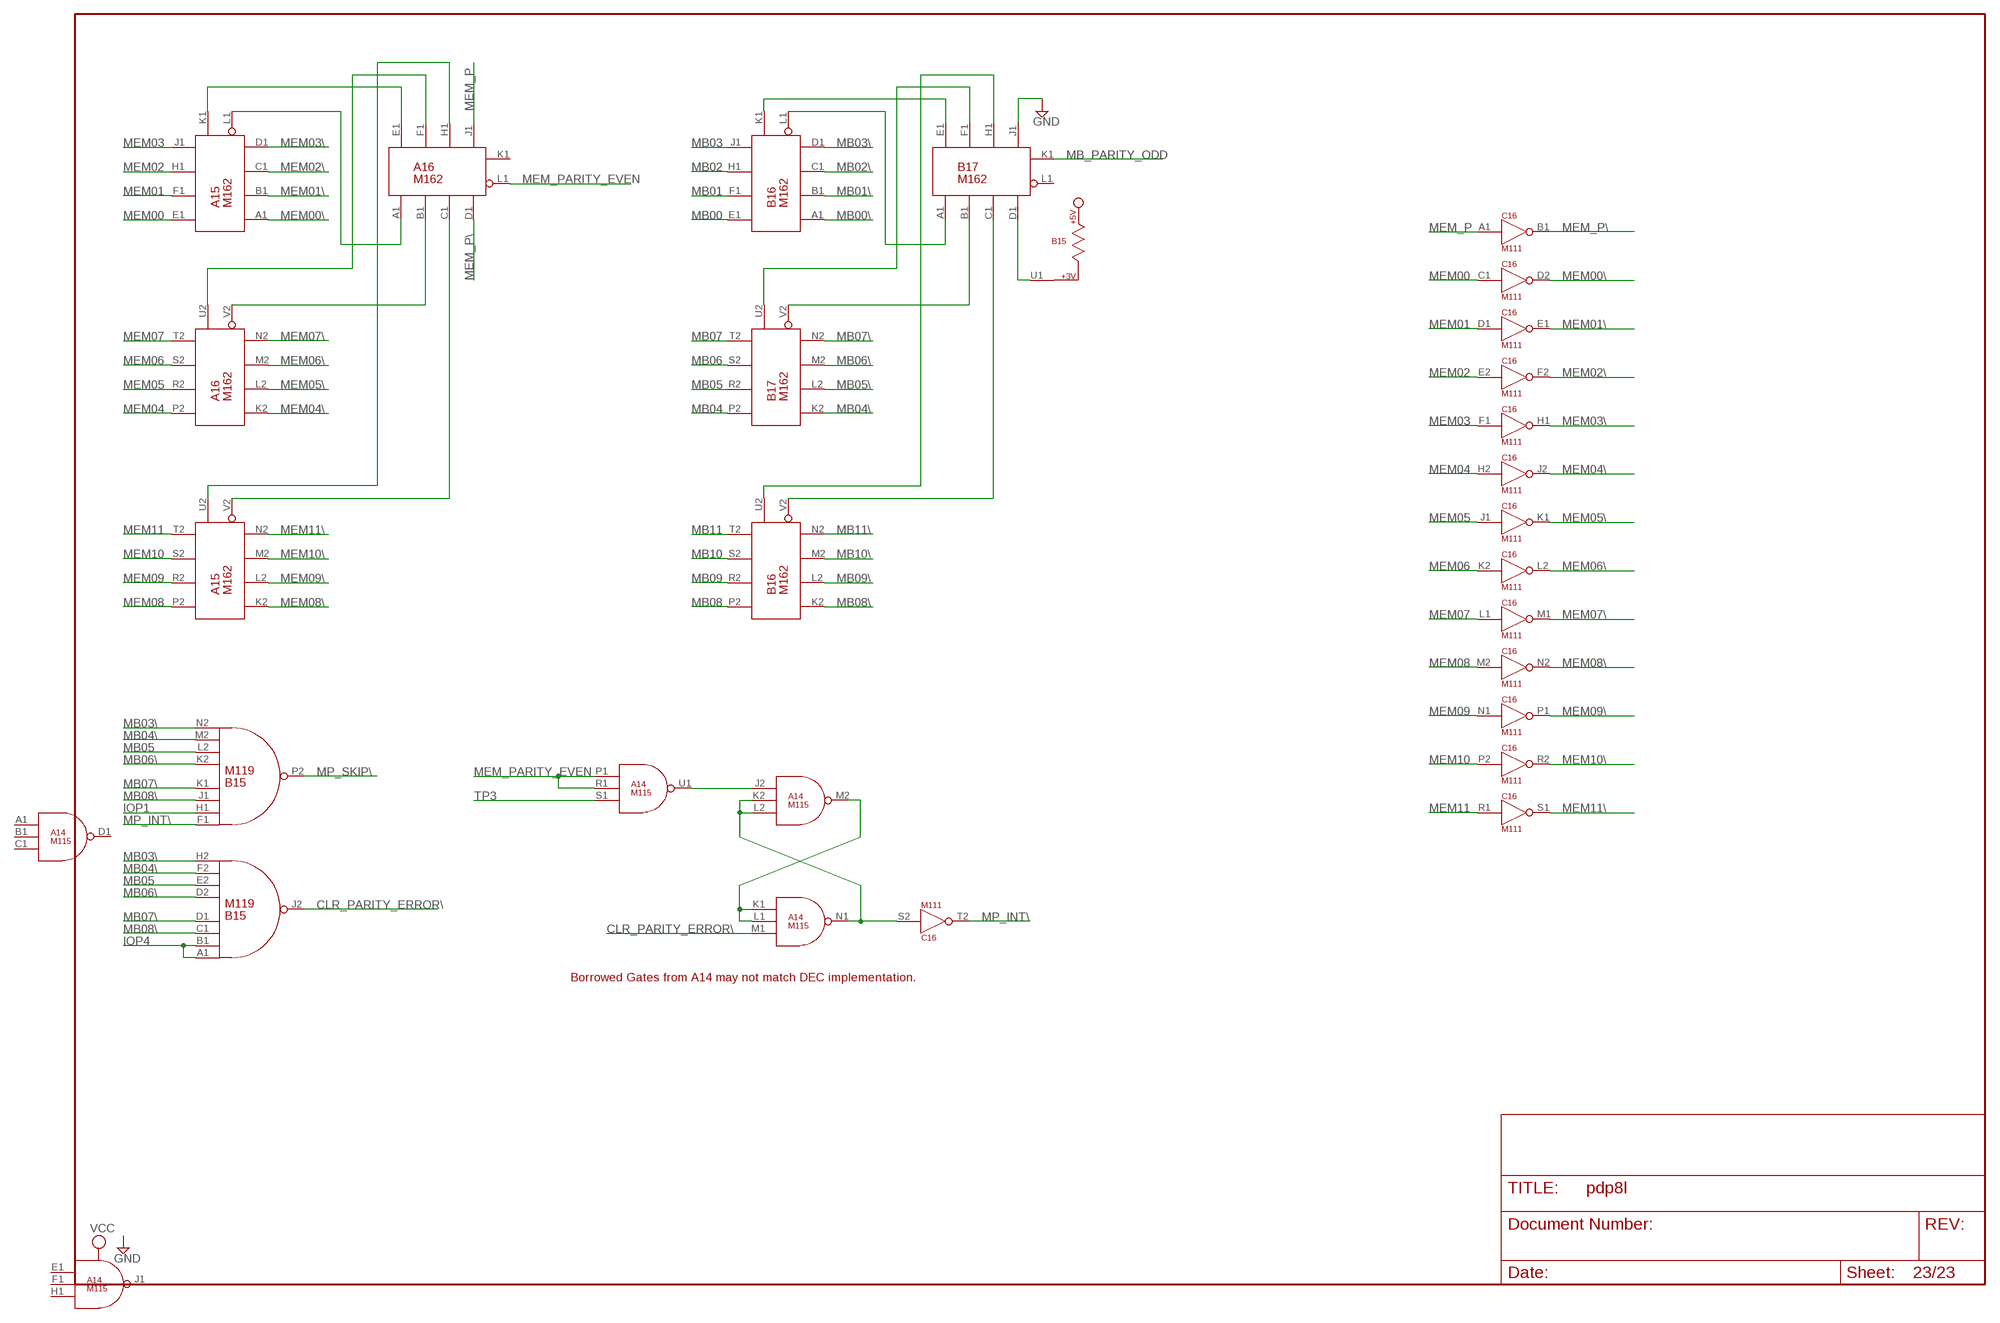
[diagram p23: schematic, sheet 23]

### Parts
A15  M162  [H807]
A16  M162  [H807]
B15  M119  [H807]
B16  M162  [H807]
B17  M162  [H807]
C16  M111  [H807]

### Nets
CLR_PARITY_ERROR\: A14.M1(N1:IN3) B15.J2(J2:OUT)
GND [Supply]: B17.J1(K1:8A) ; also sheet 1,3,8,9,10,11,12,13,14,15,16,19,20,21
IOP1: B15.H1(P2:IN2) ; also sheet 1,13,14,21,22
IOP4: B15.A1(J2:IN1) B15.B1(J2:IN2) ; also sheet 1,13,14,21,22
MB00: B16.E1(K1:1A) ; also sheet 7,12
MB00\: B16.A1(K1:1B) ; also sheet 7,16
MB01: B16.F1(K1:2A) ; also sheet 7,12
MB01\: B16.B1(K1:2B) ; also sheet 7,16
MB02: B16.H1(K1:4A) ; also sheet 7,12
MB02\: B16.C1(K1:4B) ; also sheet 7,16
MB03: B16.J1(K1:8A) ; also sheet 2,7,12
MB03\: B15.H2(J2:IN8) B15.N2(P2:IN8) B16.D1(K1:8B) ; also sheet 2,3,6,7,12,13,14,16,20,21,22
MB04: B17.P2(U2:1A) ; also sheet 3,7,12
MB04\: B15.F2(J2:IN7) B15.M2(P2:IN7) B17.K2(U2:1B) ; also sheet 3,6,7,12,13,14,20,21,22
MB05: B15.E2(J2:IN6) B15.L2(P2:IN6) B17.R2(U2:2A) ; also sheet 3,5,7,12,20
MB05\: B17.L2(U2:2B) ; also sheet 3,6,7,12,13,14,21,22
MB06: B17.S2(U2:4A) ; also sheet 3,5,7,12,14
MB06\: B15.D2(J2:IN5) B15.K2(P2:IN5) B17.M2(U2:4B) ; also sheet 3,6,7,12,13,20,21,22
MB07: B17.T2(U2:8A) ; also sheet 3,5,7,12,13,21
MB07\: B15.D1(J2:IN4) B15.K1(P2:IN4) B17.N2(U2:8B) ; also sheet 3,6,7,12,14,20,22
MB08: B16.P2(U2:1A) ; also sheet 4,5,7,12,13,22
MB08\: B15.C1(J2:IN3) B15.J1(P2:IN3) B16.K2(U2:1B) ; also sheet 4,5,6,7,12,14,16,20,21
MB09: B16.R2(U2:2A) ; also sheet 1,3,4,7,12
MB09\: B16.L2(U2:2B) ; also sheet 4,7,16
MB10: B16.S2(U2:4A) ; also sheet 1,4,7,12
MB10\: B16.M2(U2:4B) ; also sheet 4,6,7,16
MB11: B16.T2(U2:8A) ; also sheet 1,4,7,12
MB11\: B16.N2(U2:8B) ; also sheet 1,2,3,6,7,16
MB_PARITY_ODD: B17.K1(K1:ODD) ; also sheet 16
MEM00: A15.E1(K1:1A) C16.C1(D2:IN) ; also sheet 2,8,16
MEM00\: A15.A1(K1:1B) C16.D2(D2:OUT)
MEM01: A15.F1(K1:2A) C16.D1(E1:IN) ; also sheet 2,8,16
MEM01\: A15.B1(K1:2B) C16.E1(E1:OUT)
MEM02: A15.H1(K1:4A) C16.E2(F2:IN) ; also sheet 2,8,16
MEM02\: A15.C1(K1:4B) C16.F2(F2:OUT)
MEM03: A15.J1(K1:8A) C16.F1(H1:IN) ; also sheet 9,16
MEM03\: A15.D1(K1:8B) C16.H1(H1:OUT)
MEM04: A16.P2(U2:1A) C16.H2(J2:IN) ; also sheet 9,16
MEM04\: A16.K2(U2:1B) C16.J2(J2:OUT)
MEM05: A16.R2(U2:2A) C16.J1(K1:IN) ; also sheet 9,16
MEM05\: A16.L2(U2:2B) C16.K1(K1:OUT)
MEM06: A16.S2(U2:4A) C16.K2(L2:IN) ; also sheet 10,16
MEM06\: A16.M2(U2:4B) C16.L2(L2:OUT)
MEM07: A16.T2(U2:8A) C16.L1(M1:IN) ; also sheet 10,16
MEM07\: A16.N2(U2:8B) C16.M1(M1:OUT)
MEM08: A15.P2(U2:1A) C16.M2(N2:IN) ; also sheet 10,16
MEM08\: A15.K2(U2:1B) C16.N2(N2:OUT)
MEM09: A15.R2(U2:2A) C16.N1(P1:IN) ; also sheet 11,16
MEM09\: A15.L2(U2:2B) C16.P1(P1:OUT)
MEM10: A15.S2(U2:4A) C16.P2(R2:IN) ; also sheet 11,16
MEM10\: A15.M2(U2:4B) C16.R2(R2:OUT)
MEM11: A15.T2(U2:8A) C16.R1(S1:IN) ; also sheet 11,16
MEM11\: A15.N2(U2:8B) C16.S1(S1:OUT)
MEM_P: A16.J1(K1:8A) C16.A1(B1:IN) ; also sheet 16
MEM_P\: A16.D1(K1:8B) C16.B1(B1:OUT)
MEM_PARITY_EVEN: A14.P1(U1:IN1) A14.R1(U1:IN2) A16.L1(K1:EVEN)
MP_INT\: B15.F1(P2:IN1) C16.T2(T2:OUT) ; also sheet 14
MP_SKIP\: B15.P2(P2:OUT) ; also sheet 14
N$259: A15.K1(K1:ODD) A16.E1(K1:1A)
N$260: A15.L1(K1:EVEN) A16.A1(K1:1B)
N$261: A16.F1(K1:2A) A16.U2(U2:ODD)
N$262: A16.B1(K1:2B) A16.V2(U2:EVEN)
N$263: A15.V2(U2:EVEN) A16.C1(K1:4B)
N$264: A15.U2(U2:ODD) A16.H1(K1:4A)
N$265: B16.K1(K1:ODD) B17.E1(K1:1A)
N$266: B17.F1(K1:2A) B17.U2(U2:ODD)
N$406: B16.U2(U2:ODD) B17.H1(K1:4A)
N$407: B16.V2(U2:EVEN) B17.C1(K1:4B)
N$408: B17.B1(K1:2B) B17.V2(U2:EVEN)
N$409: B16.L1(K1:EVEN) B17.A1(K1:1B)
N$410: B15.U1 B17.D1(K1:8B)
N$411: A14.J2(M2:IN1) A14.U1(U1:OUT)
N$412: A14.K1(N1:IN1) A14.L1(N1:IN2) A14.M2(M2:OUT)
N$413: A14.K2(M2:IN2) A14.L2(M2:IN3) A14.N1(N1:OUT) C16.S2(T2:IN)
TP3: A14.S1(U1:IN3) ; also sheet 1,5
Unconnected: A16.K1(K1:ODD) B15.M1(V2:IN1) B15.N1(V2:IN2) B15.P1(V2:IN3) B15.R1(V2:IN4) B15.R2(V2:IN5) B15.S2(V2:IN6) B15.T2(V2:IN7) B15.U2(V2:IN8) B15.V1 B15.V2(V2:OUT) B17.L1(K1:EVEN) C16.U1(U1:OUT) C16.U2(V2:IN) C16.V1(U1:IN) C16.V2(V2:OUT)

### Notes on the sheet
- Borrowed Gates from A14 may not match DEC implementation.

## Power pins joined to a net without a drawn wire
-15V: A17.B2(-15V) A18.B2(-15V) A19.B2(-15V) A20.B2(-15V) B18.B2(-15V) B19.B2(-15V) B20.B2(-15V)
GND: A08.C2(GND) A08.T1(GND) A09.C2(GND) A09.T1(GND) A10.C2(GND) A10.T1(GND) A11.C2(GND) A11.T1(GND) A12.C2(GND) A12.T1(GND) A13.C2(GND) A13.T1(GND) A14.C2(GND) A14.T1(GND) A15.C2(GND) A15.T1(GND) A16.C2(GND) A16.T1(GND) A17.C2(GND) A17.T1(GND) A18.C2(GND) A18.T1(GND) A19.C2(GND) A19.T1(GND) A20.C2(GND) A20.T1(GND) A23.C2(C2:GND) A23.T1(T1:GND) A24.C2(C2:GND) A24.T1(T1:GND) A32.C2(GND) A32.T1(GND) A33.C2(GND) A33.T1(GND) A34.C2(GND) A34.T1(GND) A35.C2(GND) A35.T1(GND) AB02.AC2(GND) AB02.AT1(GND) AB02.BC2(GND) AB02.BT1(GND) AB03.AC2(GND) AB03.AT1(GND) AB03.BC2(GND) AB03.BT1(GND) AB04.AC2(GND) AB04.AT1(GND) AB04.BC2(GND) AB04.BT1(GND) AB05.AC2(GND) AB05.AT1(GND) AB05.BC2(GND) AB05.BT1(GND) AB06.AC2(GND) AB06.AT1(GND) AB06.BC2(GND) AB06.BT1(GND) AB07.AC2(GND) AB07.AT1(GND) AB07.BC2(GND) AB07.BT1(GND) AB29.AC2(GND) AB29.BC2(GND) AB30.AC2(GND) AB30.AT1(GND) AB30.BC2(GND) AB30.BT1(GND) AB31.AC2(GND) AB31.AT1(GND) AB31.BC2(GND) AB31.BT1(GND) B08.C2(GND) B08.T1(GND) B09.C2(GND) B09.T1(GND) B10.C2(GND) B10.T1(GND) B11.C2(GND) B11.T1(GND) B12.C2(GND) B12.T1(GND) B13.C2(GND) B13.T1(GND) B14.C2(GND) B14.T1(GND) B15.C2(GND) B15.T1(GND) B16.C2(GND) B16.T1(GND) B17.C2(GND) B17.T1(GND) B18.C2(GND) B18.T1(GND) B19.C2(GND) B19.T1(GND) B20.C2(GND) B20.T1(GND) B23.C2(C2:GND) B23.T1(T1:GND) B24.C2(C2:GND) B24.T1(T1:GND) B32.A1(A1:GND) B32.C1(C1:GND) B32.C2(GND) B32.F1(F1:GND) B32.F2(F2:GND) B32.J2(J2:GND) B32.K1(K1:GND) B32.L2(L2:GND) B32.N1(N1:GND) B32.N2(N2:GND) B32.R1(R1:GND) B32.R2(R2:GND) B32.T1(T1:GND) B32.U2(U2:GND) B33.A1(A1:GND) B33.C1(C1:GND) B33.C2(GND) B33.F1(F1:GND) B33.F2(F2:GND) B33.J2(J2:GND) B33.K1(K1:GND) B33.L2(L2:GND) B33.N1(N1:GND) B33.N2(N2:GND) B33.R1(R1:GND) B33.R2(R2:GND) B33.T1(T1:GND) B33.U2(U2:GND) B34.A1 B34.C1 B34.C2 B34.F1 B34.F2 B34.J2 B34.K1 B34.L2 B34.N1 B34.N2 B34.R1 B34.R2 B34.T1 B34.U2 B35.A1 B35.C1 B35.C2 B35.F1 B35.F2 B35.J2 B35.K1 B35.L2 B35.N1 B35.N2 B35.R1 B35.R2 B35.T1 B35.U2 B36.A1 B36.C1 B36.C2 B36.F1 B36.F2 B36.J2 B36.K1 B36.L2 B36.N1 B36.N2 B36.R1 B36.R2 B36.T1 B36.U2 C02.C2(GND) C02.T1(GND) C04.C2(GND) C04.T1(GND) C05.C2(GND) C05.T1(GND) C06.C2(GND) C06.T1(GND) C07.C2(GND) C07.T1(GND) C08.C2(GND) C08.T1(GND) C09.C2(GND) C09.T1(GND) C10.C2(GND) C10.T1(GND) C11.C2(GND) C11.T1(GND) C12.C2(GND) C12.T1(GND) C13.C2(GND) C13.T1(GND) C14.C2(GND) C14.T1(GND) C15.C2(GND) C15.T1(GND) C16.C2(GND) C16.T1(GND) C17.C2(GND) C18.C2(GND) C19.C2(GND) C23.C2(GND) C24.C2(GND) C25.C2(C2:GND) C25.T1(T1:GND) C26.C2(GND) C27.C2(GND) C27.T1(GND) C27.U1(GND) C27.V1(GND) C28.C2(GND) C28.T1(GND) C29.C2(GND) C30.C2(GND) C35.A1 C35.C1 C35.C2 C35.F1 C35.F2 C35.J2 C35.K1 C35.L2 C35.N1 C35.N2 C35.R1 C35.R2 C35.T1 C35.U2 C36.A1 C36.C1 C36.C2 C36.F1 C36.F2 C36.J2 C36.K1 C36.L2 C36.N1 C36.N2 C36.R1 C36.R2 C36.T1 C36.U2 CD03.AC2(GND) CD03.BC2(GND) D02.C2(GND) D02.T1(GND) D04.C2(GND) D04.T1(GND) D05.C2(GND) D05.T1(GND) D06.C2(GND) D06.T1(GND) D07.C2(GND) D07.T1(GND) D08.C2(GND) D08.T1(GND) D09.C2(GND) D09.T1(GND) D10.C2(GND) D10.T1(GND) D11.C2(GND) D11.T1(GND) D12.C2(GND) D12.T1(GND) D13.C2(GND) D13.T1(GND) D14.C2(GND) D14.T1(GND) D15.C2(GND) D15.T1(GND) D16.C2(GND) D16.T1(GND) D17.C2(GND) D17.T1(GND) D18.C2(GND) D19.C2(GND) D23.C2(GND) D24.C2(GND) D25.C2(C2:GND) D25.T1(T1:GND) D27.C2(GND) D27.T1(GND) D27.U1(GND) D27.V1(GND) D28.C2(GND) D28.T1(GND) D28.U1(GND) D28.V1(GND) D29.A1(A1:GND) D29.C1(C1:GND) D29.C2(GND) D29.F1(F1:GND) D29.F2(F2:GND) D29.J2(J2:GND) D29.K1(K1:GND) D29.L2(L2:GND) D29.N1(N1:GND) D29.N2(N2:GND) D29.R1(R1:GND) D29.R2(R2:GND) D29.T1(T1:GND) D29.U2(U2:GND) D30.A1(A1:GND) D30.C1(C1:GND) D30.C2(GND) D30.F1(F1:GND) D30.F2(F2:GND) D30.J2(J2:GND) D30.K1(K1:GND) D30.L2(L2:GND) D30.N1(N1:GND) D30.N2(N2:GND) D30.R1(R1:GND) D30.R2(R2:GND) D30.T1(T1:GND) D30.U2(U2:GND) D34.A1 D34.C1 D34.C2 D34.F1 D34.F2 D34.J2 D34.K1 D34.L2 D34.N1 D34.N2 D34.R1 D34.R2 D34.T1 D34.U2 D35.A1 D35.C1 D35.C2 D35.F1 D35.F2 D35.J2 D35.K1 D35.L2 D35.N1 D35.N2 D35.R1 D35.R2 D35.T1 D35.U2 D36.A1 D36.C1 D36.C2 D36.F1 D36.F2 D36.J2 D36.K1 D36.L2 D36.N1 D36.N2 D36.R1 D36.R2 D36.T1 D36.U2
VCC: A08.A2(VCC) A09.A2(VCC) A10.A2(VCC) A11.A2(VCC) A12.A2(VCC) A13.A2(VCC) A14.A2(VCC) A15.A2(VCC) A16.A2(VCC) A17.A2(VCC) A18.A2(VCC) A19.A2(VCC) A20.A2(VCC) A23.A2(C2:VCC) A24.A2(C2:VCC) A32.A2(VCC) A33.A2(VCC) A34.A2(VCC) A35.A2(VCC) AB02.AA2(VCC) AB02.BA2(VCC) AB03.AA2(VCC) AB03.BA2(VCC) AB04.AA2(VCC) AB04.BA2(VCC) AB05.AA2(VCC) AB05.BA2(VCC) AB06.AA2(VCC) AB06.BA2(VCC) AB07.AA2(VCC) AB07.BA2(VCC) AB29.AA2(VCC) AB29.BA2(VCC) AB30.AA2(VCC) AB30.BA2(VCC) AB31.AA2(VCC) AB31.BA2(VCC) B08.A2(VCC) B09.A2(VCC) B10.A2(VCC) B11.A2(VCC) B12.A2(VCC) B13.A2(VCC) B14.A2(VCC) B15.A2(VCC) B16.A2(VCC) B17.A2(VCC) B18.A2(VCC) B19.A2(VCC) B20.A2(VCC) B23.A2(C2:VCC) B24.A2(C2:VCC) B32.A2(VCC) B33.A2(VCC) C02.A2(VCC) C04.A2(VCC) C05.A2(VCC) C06.A2(VCC) C07.A2(VCC) C08.A2(VCC) C09.A2(VCC) C10.A2(VCC) C11.A2(VCC) C12.A2(VCC) C13.A2(VCC) C14.A2(VCC) C15.A2(VCC) C16.A2(VCC) C17.A2(VCC) C18.A2(VCC) C19.A2(VCC) C23.A2(VCC) C24.A2(VCC) C25.A2(C2:VCC) C26.A2(VCC) C27.A2(VCC) C28.A2(VCC) C29.A2(VCC) C30.A2(VCC) CD03.AA2(VCC) CD03.BA2(VCC) D02.A2(VCC) D04.A2(VCC) D05.A2(VCC) D06.A2(VCC) D07.A2(VCC) D08.A2(VCC) D09.A2(VCC) D10.A2(VCC) D11.A2(VCC) D12.A2(VCC) D13.A2(VCC) D14.A2(VCC) D15.A2(VCC) D16.A2(VCC) D17.A2(VCC) D18.A2(VCC) D19.A2(VCC) D23.A2(VCC) D24.A2(VCC) D25.A2(C2:VCC) D27.A2(VCC) D28.A2(VCC) D29.A2(VCC) D30.A2(VCC)

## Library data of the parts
A01 A28A A36 B01 C01 C31 C32 C34 D01 D31 D32 = dec-r:M916: Simple 36 pin connector/wire cable
A08 A09 B08 B09 D17 = dec-r:M617: 6 4-input NAND Buffers
A10 A12 A13 B10 D09 = dec-r:M160: AND-NOR Gates
A11 A14 C09 C12 C28 D04 = dec-r:M115: 8 3-input NAND Gates
A15 A16 B16 B17 = dec-r:M162: Parity Circuit
A17-A20 B18-B20 = dec-r:G020: Sense Amps
A21 A22 A27 B21 B22 B27 B28 C20 C22 C33 D20 D22 D33 = dec-r:W023: One-sided 18 pin connector/cable.
A23 A24 B23 B24 C25 D25 = dec-r:G228: Inhibit Driver
A25 A26 B25 B26 = dec-r:G624: Resistor Board
A32 A33 = dec-r:M516: Hex Positive Bus Receiver
A34 A35 B12 C07 C16 D02 D13 = dec-r:M111: Sixteen inverters.
AB02-AB07 = dec-r:M220X: PDP-8 Major Registers
AB29 = dec-r:M715: Reader Clock
AB30 = dec-r:M705: Reader Control
AB31 = dec-r:M710: Punch Control
B11 C04 C06 C08 D10 D16 = dec-r:M206X: Two sets of 3 D flip-flops
B13 C02 C05 C14 C15 D11 D12 = dec-r:M113: 10 2-input NAND Gates
B14 B15 C10 = dec-r:M119: 3 8-input NAND Gates
B32 B33 D29 D30 = dec-r:M906: Cable Terminator
B34-B36 C35 C36 D34-D36 = dec-r:M903: Two-sided Posibus cable/connector.
C11 C13 = dec-r:M117: 6 4-input NAND Gates
C17 = dec-r:M360: Variable Delay
C18 C19 C23 C24 D18 D19 D23 D24 = dec-r:G221: Memory Selector
C21 D21 D26 = dec-r:H807: Empty card slot
C26 = dec-r:M002: 15 Clamped Loads
C27 D27 D28 = dec-r:M623: 6 Dual Bus Drivers
C29 C30 = dec-r:M660: Positive Level Driver
CD03 = dec-r:M700: Manual Function Timing and Run
D05-D08 D14 D15 = dec-r:M310: Tapped Delay Line

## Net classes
1 Supply: width 0.508 mm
